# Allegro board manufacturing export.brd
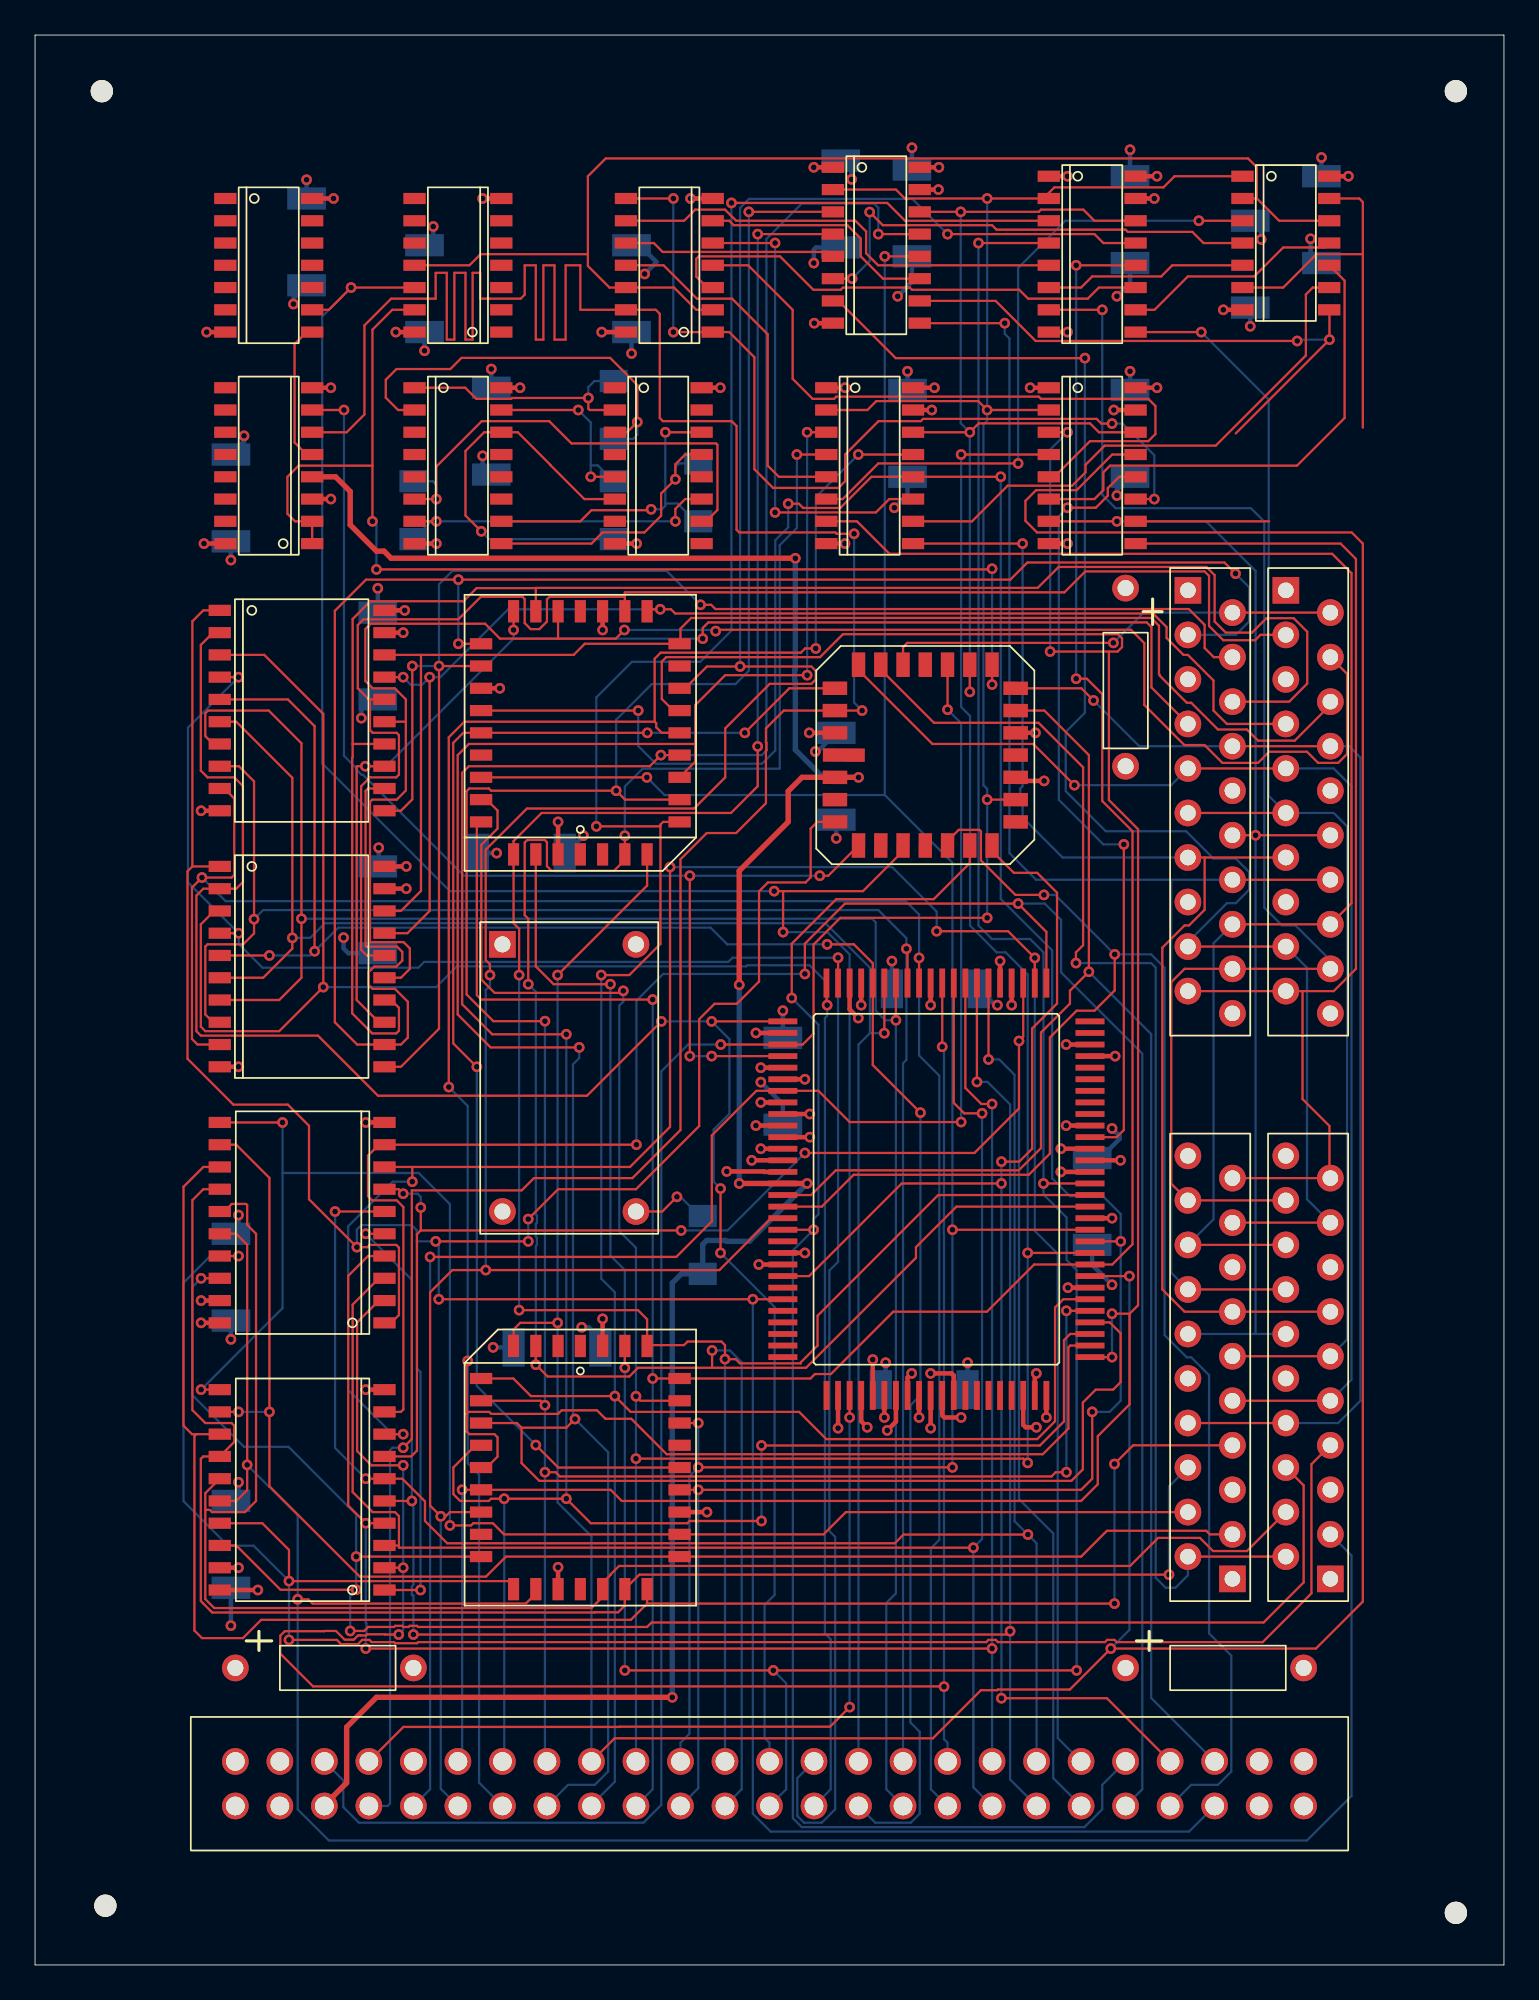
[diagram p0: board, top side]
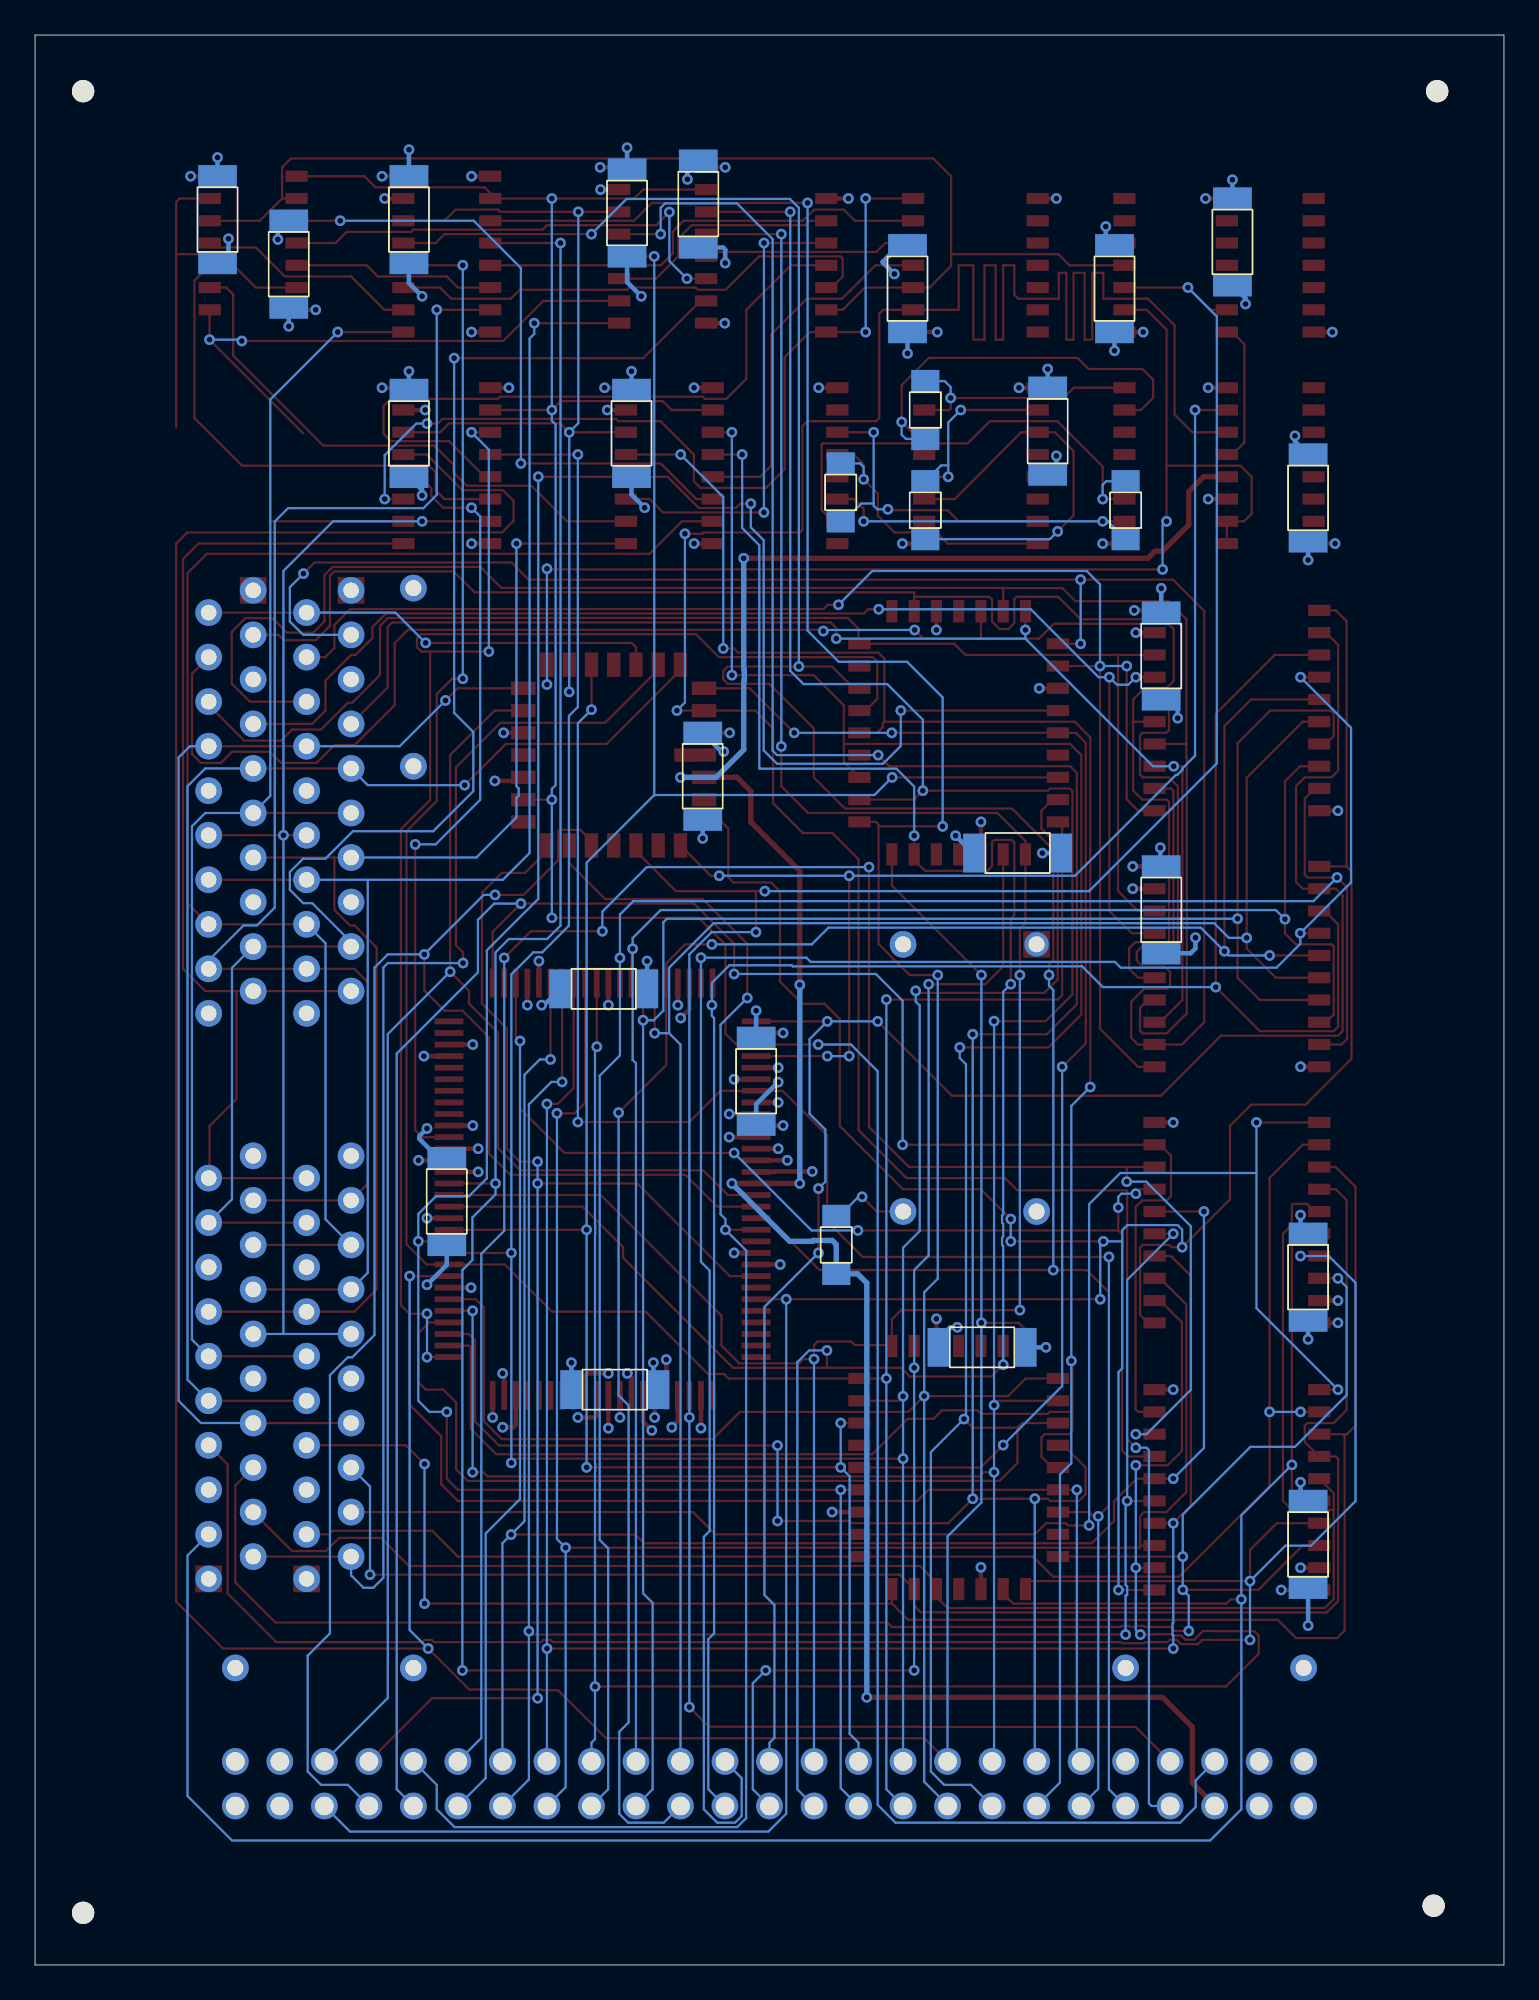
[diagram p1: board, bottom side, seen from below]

Outline 83.82 x 110.08 mm; copper layers: TOP, GND, VCC, BOTTOM. Coordinates in mm from the lower left corner of the outline.
Outline path: 0,110.08 83.82,110.08 83.82,0 0,0 0,110.08

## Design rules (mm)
constraint set DEFAULT: min track width 0.127
net group @PROJECT1_LIB.ESDESIGN(S_UPREV1: nets RA0 RA1 RA2 RA3 RA4 RA5 RA6 RA7 RA8 RA9 RA10 RA11 RA12 RA13 RA14 RA15
net group @PROJECT1_LIB.ESDESIGN(S_UPREV2: nets DATA0 DATA1 DATA2 DATA3 DATA4 DATA5 DATA6 DATA7 DATA8 DATA9 DATA10 DATA11 DATA12 DATA13 DATA14 DATA15
net group @PROJECT1_LIB.ESDESIGN(S_UPREV3: nets ADDR0 ADDR1 ADDR2 ADDR3 ADDR4 ADDR5 ADDR6 ADDR7
net group @PROJECT1_LIB.ESDESIGN(SCH_1):A: nets A1 A2 A3 A4 A5 A6 A7 A8 A9 A10 A11 A12 A13 A14 A15 A16
net group @PROJECT1_LIB.ESDESIGN(SCH_1):D: nets D0 D1 D2 D3 D4 D5 D6 D7 D8 D9 D10 D11 D12 D13 D14 D15
net group CLOCK: nets CLK1+ CLK1- CLK2+ CLK2- CLK3+ CLK3- CLK4+ CLK4-
net group SYNC: nets CLK2
nets with their own width: min track width 0.254; nets GND VCC

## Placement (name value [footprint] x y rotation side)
C1  .01UF  [SMDCAP]  50.8 32.82 0 bottom
C2  .01UF  [SMDCAP]  49.78 87.3 270 bottom
C3  .01UF  [SMDCAP]  62.48 99.49 270 bottom
C4  .01UF  [SMDCAP]  50.04 99.87 270 bottom
C5  22UF  [CAP400]  62.23 78.54 180 top
C6  .01UF  [SMDCAP]  45.97 100.51 90 bottom
C7  .01UF  [SMDCAP]  62.48 87.3 270 bottom
C8  22UF  [CAP400]  11.43 16.94 270 top
C9  .01UF  [SMDCAP]  60.33 43.61 90 bottom
C10  .01UF  [SMDCAP]  51.44 55.68 0 bottom
C11  22UF  [CAP400]  62.23 16.94 270 top
C12  .01UF  [SMDCAP]  26.04 87.43 270 bottom
C13  .01UF  [SMDCAP]  22.23 95.68 90 bottom
C14  1UF  [SMDCAP]  15.49 98.22 270 bottom
C15  .01UF  [SMDCAP]  11.18 83.74 90 bottom
C16  .01UF  [SMDCAP]  42.67 50.47 90 bottom
C17  1UF  [SMDCAP]  34.04 95.68 90 bottom
C18  .01UF  [SMDCAP]  29.72 35.23 180 bottom
C19  .01UF  [SMDCAP]  11.18 24.05 90 bottom
C20  1UF  [SMDCAP]  19.56 60.12 270 bottom
C21  .01UF  [SMDCAP]  27.69 63.42 180 bottom
C22  .01UF  [SMDCAP]  11.18 39.29 90 bottom
C23  .01UF  [SMDCAP]  19.56 74.6 270 bottom
C24  .01UF  [SMDCAP]  73.41 99.49 270 bottom
C25  .01UF  [SMDCAP]  45.72 67.74 270 bottom
C26  .01UF  [SMDCAP]  69.34 96.95 270 bottom
J1  -  [CONN50]  11.43 9.07 0 top
NOREF  -  [unnamed]  81.08 106.88 0 top
NOREF#2  -  [#2]  -43.18 -65.61 0 top
NOREF#3  -  [#2]  129.54 56.31 0 top
NOREF#4  -  [unnamed]  3.81 106.88 0 top
NOREF#5  -  [unnamed]  4.01 3.38 0 top
NOREF#6  -  [unnamed]  81.08 2.97 0 top
R1  10K  [SMDRES]  38.1 41.07 270 bottom
R2  10K  [SMDRES]  33.02 88.7 270 bottom
R3  10K  [SMDRES]  33.02 82.98 90 bottom
R4  10K  [SMDRES]  21.59 82.98 270 bottom
R5  10K  [SMDRES]  37.85 84 90 bottom
U1  ***  [SOIC16]  47.62 85.52 0 top
U2  ***  [SOIC16]  60.33 97.59 0 top
U3  ***  [SOIC16]  48.01 98.09 0 top
U4  ***  [SOIC16]  60.33 85.52 0 top
U5  ***  [ZIP20]  68.33 22.02 180 top
U6  ***  [ZIP20]  73.91 22.02 180 top
U7  ***  [ZIP20]  65.79 78.41 0 top
U8  ***  [ZIP20]  71.37 78.41 0 top
U9  ***  [SOIC14]  13.34 96.95 0 top
U10  ***  [SOIC16]  13.34 85.52 180 top
U11  ***  [PQFP100]  51.44 44.25 0 top
U12  ***  [SOIC14]  36.2 96.95 180 top
U13  ***  [PLCC32]  31.11 28.37 0 top
U14  ***  [SOIC20W]  15.24 27.1 180 top
U15  ***  [SOIC20W]  15.24 56.95 0 top
U16  ***  [PLCC32]  31.11 70.28 180 top
U17  ***  [SOIC20W]  15.24 42.34 180 top
U18  ***  [SOIC20W]  15.24 71.55 0 top
U19  ***  [LCC28]  50.8 69.01 90 top
U20  ***  [SOIC14]  71.37 98.22 0 top
U21  ***  [SOIC14]  24.13 96.95 180 top
U22  ***  [SOIC16]  35.56 85.52 0 top
U23  ***  [SOIC16]  24.13 85.52 0 top
Y1  ***  [CRYS14]  26.67 58.22 0 top

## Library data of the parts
C1-C4 C6 C7 C9 C10 C12 C13 C15 C16 C18 C19 C21-C26 = CAP: Tolerance: ***; User Part Number: 21505-267-01; part number: CAP-.01UF
C5 C8 C11 = CAP: Tolerance: ***; User Part Number: 21505-274-01; part number: CAP-22UF
C14 C17 C20 = CAP: Tolerance: ***; User Part Number: 21503-260-12; part number: CAP-1UF
J1 = CONNECTOR: User Part Number: ***
R1-R5 = PRES: Tolerance: ***; User Part Number: 24707-008-73; part number: PRES-10K
U1-U4 = 74F153: User Part Number: CDS_K006; part number: 74F153_SOIC-BASE; room: ADDR
U5-U8 = M5M44C256P-10: User Part Number: CDS_032; part number: M5M44C256P-10_ZIP-BASE; room: DRAM
U9 = 74F04: User Part Number: CDS_K002; part number: 74F04_SOIC-BASE
U10 = 74F109: User Part Number: CDS_K004; part number: 74F109_SOIC-BASE
U11 = I80386S: User Part Number: CDS_011; part number: I80386S_PQFP-BASE
U12 = 74F393: User Part Number: CDS_K012; alternate symbols: (TOP:DIP14_3;BOTTOM:SOIC14_PE); part number: 74F393_SOIC-BASE
U13 U16 = 27C256: User Part Number: CDS_002; part number: 27C256_PLCC-BASE
U14 U15 U17 U18 = 74F245: User Part Number: CDS_K008; part number: 74F245_SOIC-BASE
U19 = PAL20R8: User Part Number: cds_028; part number: PAL20R8_LCC-BASE
U20 = 74F393: User Part Number: CDS_K012; part number: 74F393_SOIC-BASE
U21 = 74F32: User Part Number: CDS_K010; part number: 74F32_SOIC-BASE
U22 = DS90LV031TM
U23 = DS90LV032TM
Y1 = OSC

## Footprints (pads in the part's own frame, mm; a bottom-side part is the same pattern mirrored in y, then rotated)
CAP400
  round 1.524 hole 0.914: 1(0,0) 2(0,10.16)
CONN50
  round 1.524 hole 1.067: 1(0,0) 2(0,2.54) 3(2.54,0) 4(2.54,2.54) 5(5.08,0) 6(5.08,2.54) 7(7.62,0) 8(7.62,2.54) 9(10.16,0) 10(10.16,2.54) 11(12.7,0) 12(12.7,2.54) 13(15.24,0) 14(15.24,2.54) 15(17.78,0) 16(17.78,2.54) 17(20.32,0) 18(20.32,2.54) 19(22.86,0) 20(22.86,2.54) 21(25.4,0) 22(25.4,2.54) 23(27.94,0) 24(27.94,2.54) 25(30.48,0) 26(30.48,2.54) 27(33.02,0) 28(33.02,2.54) 29(35.56,0) 30(35.56,2.54) 31(38.1,0) 32(38.1,2.54) 33(40.64,0) 34(40.64,2.54) 35(43.18,0) 36(43.18,2.54) 37(45.72,0) 38(45.72,2.54) 39(48.26,0) 40(48.26,2.54) 41(50.8,0) 42(50.8,2.54) 43(53.34,0) 44(53.34,2.54) 45(55.88,0) 46(55.88,2.54) 47(58.42,0) 48(58.42,2.54) 49(60.96,0) 50(60.96,2.54)
CRYS14
  rect 1.524x1.524 hole 0.914: 1(0,0)
  round 1.524 hole 0.914: 7(0,-15.24) 8(7.62,-15.24) 14(7.62,0)
LCC28
  rect 0.762x2.388 smd rot 179.7: 1(0,4.648)
  rect 0.762x1.397 smd rot 179.7: 2(-1.27,5.156) 12(-3.81,-5.156) 13(-2.54,-5.156) 14(-1.27,-5.156) 17(2.54,-5.156) 18(3.81,-5.156)
  rect 0.762x1.397 smd: 3(-2.54,5.156) 4(-3.81,5.156) 15(0,-5.156) 16(1.27,-5.156) 26(3.81,5.156) 27(2.54,5.156) 28(1.27,5.156)
  rect 0.762x1.397 smd rot 89.7: 5(-5.156,3.81) 6(-5.156,2.54) 7(-5.156,1.27) 8(-5.156,0) 9(-5.156,-1.27)
  rect 1.397x0.762 smd: 10(-5.156,-2.54) 11(-5.156,-3.81) 19(5.156,-3.81) 20(5.156,-2.54) 21(5.156,-1.27) 22(5.156,0) 23(5.156,1.27) 24(5.156,2.54) 25(5.156,3.81)
PLCC32
  rect 0.635x1.27 smd: 1(0,6.934) 2(-1.27,6.934) 3(-2.54,6.934) 4(-3.81,6.934) 14(-3.81,-6.934) 15(-2.54,-6.934) 16(-1.27,-6.934) 17(0,-6.934) 18(1.27,-6.934) 19(2.54,-6.934) 20(3.81,-6.934) 30(3.81,6.934) 31(2.54,6.934) 32(1.27,6.934)
  rect 1.27x0.635 smd: 5(-5.664,5.08) 6(-5.664,3.81) 7(-5.664,2.54) 8(-5.664,1.27) 9(-5.664,0) 10(-5.664,-1.27) 11(-5.664,-2.54) 12(-5.664,-3.81) 13(-5.664,-5.08) 21(5.664,-5.08) 22(5.664,-3.81) 23(5.664,-2.54) 24(5.664,-1.27) 25(5.664,0) 26(5.664,1.27) 27(5.664,2.54) 28(5.664,3.81) 29(5.664,5.08)
PQFP100
  rect 1.651x0.33 smd: 1(-8.763,9.576) 2(-8.763,8.915) 3(-8.763,8.255) 4(-8.763,7.595) 5(-8.763,6.934) 6(-8.763,6.274) 7(-8.763,5.613) 8(-8.763,4.953) 9(-8.763,4.293) 10(-8.763,3.632) 11(-8.763,2.972) 12(-8.763,2.311) 13(-8.763,1.651) 14(-8.763,0.991) 15(-8.763,0.33) 16(-8.763,-0.33) 17(-8.763,-0.991) 18(-8.763,-1.651) 19(-8.763,-2.311) 20(-8.763,-2.972) 21(-8.763,-3.632) 22(-8.763,-4.293) 23(-8.763,-4.953) 24(-8.763,-5.613) 25(-8.763,-6.274) 26(-8.763,-6.934) 27(-8.763,-7.595) 28(-8.763,-8.255) 29(-8.763,-8.915) 30(-8.763,-9.576) 51(8.763,-9.576) 52(8.763,-8.915) 53(8.763,-8.255) 54(8.763,-7.595) 55(8.763,-6.934) 56(8.763,-6.274) 57(8.763,-5.613) 58(8.763,-4.953) 59(8.763,-4.293) 60(8.763,-3.632) 61(8.763,-2.972) 62(8.763,-2.311) 63(8.763,-1.651) 64(8.763,-0.991) 65(8.763,-0.33) 66(8.763,0.33) 67(8.763,0.991) 68(8.763,1.651) 69(8.763,2.311) 70(8.763,2.972) 71(8.763,3.632) 72(8.763,4.293) 73(8.763,4.953) 74(8.763,5.613) 75(8.763,6.274) 76(8.763,6.934) 77(8.763,7.595) 78(8.763,8.255) 79(8.763,8.915) 80(8.763,9.576)
  rect 0.33x1.651 smd: 31(-6.274,-11.76) 32(-5.613,-11.76) 33(-4.953,-11.76) 34(-4.293,-11.76) 35(-3.632,-11.76) 36(-2.972,-11.76) 37(-2.311,-11.76) 38(-1.651,-11.76) 39(-0.991,-11.76) 40(-0.33,-11.76) 41(0.33,-11.76) 42(0.991,-11.76) 43(1.651,-11.76) 44(2.311,-11.76) 45(2.972,-11.76) 46(3.632,-11.76) 47(4.293,-11.76) 48(4.953,-11.76) 49(5.613,-11.76) 50(6.274,-11.76) 81(6.274,11.76) 82(5.613,11.76) 83(4.953,11.76) 84(4.293,11.76) 85(3.632,11.76) 86(2.972,11.76) 87(2.311,11.76) 88(1.651,11.76) 89(0.991,11.76) 90(0.33,11.76) 91(-0.33,11.76) 92(-0.991,11.76) 93(-1.651,11.76) 94(-2.311,11.76) 95(-2.972,11.76) 96(-3.632,11.76) 97(-4.293,11.76) 98(-4.953,11.76) 99(-5.613,11.76) 100(-6.274,11.76)
SMDCAP
  rect 1.27x2.21 smd: 1(-2.54,0) 2(2.413,0)
SMDRES
  rect 1.27x1.6 smd: 1(-1.651,0) 2(1.651,0)
SOIC14
  rect 1.27x0.635 smd: 1(-2.477,3.81) 2(-2.477,2.54) 3(-2.477,1.27) 4(-2.477,0) 5(-2.477,-1.27) 6(-2.477,-2.54) 7(-2.477,-3.81) 8(2.477,-3.81) 9(2.477,-2.54) 10(2.477,-1.27) 11(2.477,0) 12(2.477,1.27) 13(2.477,2.54) 14(2.477,3.81)
SOIC16
  rect 1.27x0.635 smd: 1(-2.477,4.445) 2(-2.477,3.175) 3(-2.477,1.905) 4(-2.477,0.635) 5(-2.477,-0.635) 6(-2.477,-1.905) 7(-2.477,-3.175) 8(-2.477,-4.445) 9(2.477,-4.445) 10(2.477,-3.175) 11(2.477,-1.905) 12(2.477,-0.635) 13(2.477,0.635) 14(2.477,1.905) 15(2.477,3.175) 16(2.477,4.445)
SOIC20W
  rect 1.27x0.635 smd: 1(-4.699,5.715) 2(-4.699,4.445) 3(-4.699,3.175) 4(-4.699,1.905) 5(-4.699,0.635) 6(-4.699,-0.635) 7(-4.699,-1.905) 8(-4.699,-3.175) 9(-4.699,-4.445) 10(-4.699,-5.715) 11(4.699,-5.715) 12(4.699,-4.445) 13(4.699,-3.175) 14(4.699,-1.905) 15(4.699,-0.635) 16(4.699,0.635) 17(4.699,1.905) 18(4.699,3.175) 19(4.699,4.445) 20(4.699,5.715)
unnamed
  round 1.27 hole 6.35 unplated: (0,0)
ZIP20
  rect 1.524x1.524 hole 0.889: 1(0,0)
  round 1.524 hole 0.889: 2(2.54,-1.27) 3(0,-2.54) 4(2.54,-3.81) 5(0,-5.08) 6(2.54,-6.35) 7(0,-7.62) 8(2.54,-8.89) 9(0,-10.16) 10(2.54,-11.43) 11(0,-12.7) 12(2.54,-13.97) 13(0,-15.24) 14(2.54,-16.51) 15(0,-17.78) 16(2.54,-19.05) 17(0,-20.32) 18(2.54,-21.59) 19(0,-22.86) 20(2.54,-24.13)

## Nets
GND: C1.2(B<0>) C2.2(B<0>) C3.2(B<0>) C4.2(B<0>) C5.2(B<0>) C6.2(B<0>) C7.2(B<0>) C8.2(B<0>) C9.2(B<0>) C10.2(B<0>) C11.2(B<0>) C12.2(B<0>) C13.2(B<0>) C14.2(B<0>) C15.2(B<0>) C16.2(B<0>) C17.2(B<0>) C18.2(B<0>) C19.2(B<0>) C20.2(B<0>) C21.2(B<0>) C22.2(B<0>) C23.2(B<0>) C24.2(B<0>) C25.2(B<0>) C26.2(B<0>) J1.47 J1.48 J1.49 J1.50 U1.1 U1.8 U1.15 U2.1 U2.8 U2.15 U3.1 U3.8 U3.15 U4.1 U4.8 U4.15 U5.1 U5.5 U5.20 U6.1 U6.5 U6.20 U7.1 U7.5 U7.20 U8.1 U8.5 U8.20 U9.7 U10.3 U10.8 U11.2 U11.5 U11.11 U11.12 U11.13 U11.14 U11.22 U11.35 U11.37 U11.38 U11.40 U11.41 U11.49 U11.50 U11.63 U11.67 U11.68 U11.77 U11.78 U11.85 U11.98 U12.7 U13.16 U13.23 U14.10 U14.19 U15.10 U15.19 U16.16 U16.23 U17.10 U17.19 U18.10 U18.19 U19.14 U19.16(OE*) U20.7 U21.7 U22.8 U23.8 Y1.1 Y1.7
VCC: C1.1 C2.1 C3.1 C4.1 C5.1 C6.1 C7.1 C8.1 C9.1 C10.1 C11.1 C12.1 C13.1 C14.1 C15.1 C16.1 C17.1 C18.1 C19.1 C20.1 C21.1 C22.1 C23.1 C24.1 C25.1 C26.1 J1.1 J1.2 J1.3 J1.4 U1.16 U2.16 U3.16 U4.16 U5.15 U6.15 U7.15 U8.15 U9.14 U10.16 U11.6 U11.8 U11.9 U11.10 U11.21 U11.32 U11.34 U11.36 U11.39 U11.42 U11.48 U11.57 U11.69 U11.71 U11.84 U11.91 U11.97 U12.14 U13.32 U14.20 U15.20 U16.32 U17.20 U18.20 U19.28 U20.14 U21.14 U22.16 U23.16 Y1.14
A1: J1.11 U2.13 U11.18 U13.11 U16.11
A2: J1.12 U4.3 U11.51 U13.10 U16.10
A3: J1.13 U1.13 U11.52 U13.9 U16.9
A4: J1.14 U3.13 U11.53 U13.8 U16.8
A5: J1.15 U1.3 U11.54 U13.7 U16.7
A6: J1.16 U3.3 U11.55 U13.6 U16.6
A7: J1.17 U2.3 U11.56 U13.5 U16.5
A8: J1.18 U4.13 U11.58 U13.4 U16.4
A9: J1.19 U2.12 U11.59 U13.29 U16.29
A10: J1.20 U4.4 U11.60 U13.28 U16.28
A11: J1.21 U1.12 U11.61 U13.24 U16.24
A12: J1.22 U3.12 U11.62 U13.27 U16.27
A13: J1.23 U1.4 U11.64 U13.3 U16.3
A14: J1.24 U3.4 U11.65 U13.30 U16.30
A15: J1.25 U2.4 U11.66 U13.31 U16.31
A16: U4.12 U11.70
ADDR0: U2.9 U5.11 U6.11 U7.11 U8.11
ADDR1: U4.7(Y<0>) U5.12 U6.12 U7.12 U8.12
ADDR2: U1.9 U5.13 U6.13 U7.13 U8.13
ADDR3: U3.9 U5.14 U6.14 U7.14 U8.14
ADDR4: U1.7(Y<0>) U5.16 U6.16 U7.16 U8.16
ADDR5: U3.7(Y<0>) U5.17 U6.17 U7.17 U8.17
ADDR6: U2.7(Y<0>) U5.18 U6.18 U7.18 U8.18
ADDR7: U4.9 U5.19 U6.19 U7.19 U8.19
ADSL: J1.46 U11.16 U19.17
BHEL: J1.42 U11.19 U19.10
BLEL: J1.43 U11.17 U19.9
CAS0L: U5.2 U6.2 U19.24
CAS1L: U7.2 U8.2 U19.23
CLEAR: U10.1 U10.2 U19.19 U21.13
CLK1+: R2.1 U22.2 U23.1
CLK1-: R2.2(B<0>) U22.3 U23.2
CLK2: J1.5 R1.2(B<0>) U10.4 U11.15 U19.2
CLK2+: R3.1 U22.6 U23.14
CLK2-: R3.2(B<0>) U22.5 U23.15
CLK3+: R4.1 U22.10 U23.6
CLK3-: R4.2(B<0>) U22.11 U23.7
CLK4+: R5.1 U22.14 U23.10
CLK4-: R5.2(B<0>) U22.13 U23.9
CLRCNT: U12.2 U12.12 U20.2 U20.12 U21.11
D0: J1.26 U11.1 U15.2 U18.2
D1: J1.27 U11.100 U15.3 U18.3
D2: J1.28 U11.99 U15.4 U18.4
D3: J1.29 U11.96 U15.5 U18.5
D4: J1.30 U11.95 U15.6 U18.6
D5: J1.31 U11.94 U15.7 U18.7
D6: J1.32 U11.93 U15.8 U18.8
D7: J1.33 U11.92 U15.9 U18.9
D8: J1.34 U11.90 U14.2 U17.2
D9: J1.35 U11.89 U14.3 U17.3
D10: J1.36 U11.88 U14.4 U17.4
D11: J1.37 U11.87 U14.5 U17.5
D12: J1.38 U11.86 U14.6 U17.6
D13: J1.39 U11.83 U14.7 U17.7
D14: J1.40 U11.82 U14.8 U17.8
D15: J1.41 U11.81 U14.9 U17.9
DATA0: U8.6 U15.18(B<0>) U16.13 U18.18(B<0>)
DATA1: U8.7 U15.17 U16.14 U18.17
DATA2: U8.3 U15.16 U16.15 U18.16
DATA3: U8.4 U15.15 U16.18 U18.15
DATA4: U7.6 U15.14 U16.19 U18.14
DATA5: U7.7 U15.13 U16.20 U18.13
DATA6: U7.3 U15.12 U16.21 U18.12
DATA7: U7.4 U15.11 U16.22 U18.11
DATA8: U6.6 U13.13 U14.18(B<0>) U17.18(B<0>)
DATA9: U6.7 U13.14 U14.17 U17.17
DATA10: U6.3 U13.15 U14.16 U17.16
DATA11: U6.4 U13.18 U14.15 U17.15
DATA12: U5.6 U13.19 U14.14 U17.14
DATA13: U5.7 U13.20 U14.13 U17.13
DATA14: U5.3 U13.21 U14.12 U17.12
DATA15: U5.4 U13.22 U14.11 U17.11
HLDA: J1.6 U1.2 U2.2 U3.2 U4.2 U11.3 U19.13 U20.1
M_IO: J1.44 U11.23 U19.11
MUXSOL: U1.14 U2.14 U3.14 U4.14 U19.20
PCLK: J1.7 U10.6(Q<0>) U12.13 U19.27
RA0: U2.11 U12.3
RA1: U4.5 U12.4
RA2: U1.11 U12.5
RA3: U3.11 U12.6(Q<3>)
RA4: U1.5 U12.11
RA5: U3.5 U12.10
RA6: U2.5 U12.9
RA7: U4.11 U12.1 U12.8
RA8: U2.10 U20.11
RA9: U4.6 U20.10
RA10: U1.10 U20.9
RA11: U3.10 U20.8
RA12: U1.6 U20.3
RA13: U3.6 U20.4
RA14: U2.6 U20.5
RA15: U4.10 U20.6(Q<3>) U20.13
RASL: U5.9 U6.9 U7.9 U8.9 U19.25
RDYL: J1.9(A<9>) U11.7 U19.21
REF: U10.7 U11.4 U19.5
RESET: J1.8 U9.9 U11.33 U19.7 U21.12
RESETL: U9.8 U10.5
ROMOEL: U13.25 U16.25 U19.26
UNNAMED_1_OSC_I31_B: R1.1 Y1.8(B)
W_R: J1.45 U11.25(W/R*) U14.1 U15.1 U17.1 U18.1 U19.4
WEL: U5.8(WE*) U6.8(WE*) U7.8(WE*) U8.8(WE*) U19.18

Pads without a net: J1 10; U5 10; U6 10; U7 10; U8 10; U9 1 2 3 4 5 6 10 11 12 13; U10 9 10 11 12 13 14 15; U11 20 24 26 27 28 29 30 31 43 44 45 46 47 72 73 74 75 76 79 80; U13 1 2 12 17 26; U16 1 2 12 17 26; U19 1 3 6 8 12 15 22; U21 1 2 3 4 5 6 8 9 10; U22 1 4 7 9 12 15; U23 3 4 5 11 12 13

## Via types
v1: diameter 0.61, hole 0.33, TOP to BOTTOM, 390 vias

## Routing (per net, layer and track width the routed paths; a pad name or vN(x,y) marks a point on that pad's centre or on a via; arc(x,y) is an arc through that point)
GND: length 353.4
  TOP w0.254: U11.41 51.77,31.36 51.89,31.23 v1(52.84,31.23) ; U20.7 v1(67.81,94.41) ; U11.50 v1(57.71,31.23) ; U19.16 v1(57.09,70.28) ; U18.10 v1(9.47,65.84) ; U12.7 v1(37.41,100.76) ; U4.1 v1(56.78,89.97) ; U2.15 v1(63.87,100.76) ; U11.85 v1(55.07,57.26) ; U11.77 v1(61.63,51.84) ; U16.16 v1(32.38,76.15) ; U11.68 v1(61.94,45.9) ; U13.23 v1(38.34,25.83) ; U11.63 v1(61.46,42.6) ; U16.23 v1(26.52,72.82) ; U11.35 v1(47.8,34.53) ; v1(57.14,33.74) 57.05,33.66 U11.49 ; U22.8 v1(34.33,81.08) ; U14.10 v1(18.87,32.82) ; U3.15 v1(51.55,101.27) ; U11.67 v1(58.53,45.24) ; v1(48.63,30.49) 49.12,30.99 U11.37 ; U23.8 v1(22.9,81.08) ; U11.5 v1(41.41,51.18) ; v1(57.58,67.54) 56.16,67.54 U19.14 ; U1.8 v1(46.22,81.08) ; U15.19 v1(21.18,61.39) ; U11.38 49.78,33.5 v1(50.03,33.74) ; U11.13 v1(40.89,45.9) ; U13.16 v1(29.84,22.68) ; U4.8 v1(58.92,81.08) ; U17.19 v1(9.47,37.9) ; U11.40 v1(51.1,30.62) ; U2.8 v1(58.92,93.14) ; U1.15 v1(51.17,88.7) ; U9.7 v1(9.79,93.14) ; U1.1 v1(46.22,89.97) ; U4.15 v1(61.56,88.7) ; U3.8 v1(44.46,93.65) ; U18.19 v1(21.01,76) ; U10.3 v1(16.88,83.62) ; U11.22 v1(41.3,39.95) ; U11.98 46.48,54.51 v1(46.98,54.01) ; U15.10 v1(11.61,51.23) ; U11.78 v1(58.84,52.5) ; U11.11 v1(44.21,47.22) ; U14.19 v1(11.61,22.66) ; U11.2 v1(41.14,53.16) ; U21.7 v1(25.54,100.76) ; v1(39.47,45.26) 41.59,45.26 41.62,45.24 U11.14 ; U10.8 v1(16.88,89.97) ; U3.1 v1(44.44,102.54) ; U11.12 v1(41.41,46.56) ; U17.10 v1(18.87,48.06) ; U2.1 v1(58.92,102.03)
  GND w0.254: v1(41.3,39.95) 41.71,40.36 ; v1(41.3,39.95) 41.71,39.54 ; v1(41.3,39.95) 40.89,40.36 ; v1(41.3,39.95) 40.89,39.54 ; v1(61.46,47.71) 61.87,48.12 ; v1(61.46,47.71) 61.87,47.3 ; v1(61.46,47.71) 61.04,48.12 ; v1(61.46,47.71) 61.04,47.3 ; 45.31,63.85 v1(45.72,64.26) ; v1(45.72,64.26) 46.13,63.85 ; v1(45.72,64.26) 46.13,64.67 ; v1(45.72,64.26) 45.31,64.67 ; 49.61,34.15 v1(50.03,33.74) ; v1(50.03,33.74) 50.44,33.33 ; v1(50.03,33.74) 49.61,33.33 ; v1(50.03,33.74) 50.44,34.15 ; v1(14.74,94.74) 15.16,94.33 ; v1(14.74,94.74) 15.16,95.15 ; v1(14.74,94.74) 14.33,94.33 ; v1(14.74,94.74) 14.33,95.15 ; 37.93,25.42 v1(38.34,25.83) ; v1(38.34,25.83) 38.75,25.42 ; v1(38.34,25.83) 37.93,26.24 ; v1(38.34,25.83) 38.75,26.24 ; v1(55.07,57.26) 55.48,56.85 ; v1(55.07,57.26) 54.66,57.67 ; v1(55.07,57.26) 55.48,57.67 ; v1(55.07,57.26) 54.66,56.85 ; v1(46.6,101.85) 47.01,102.26 ; v1(46.6,101.85) 46.19,102.26 ; v1(46.6,101.85) 46.19,101.44 ; v1(46.6,101.85) 47.01,101.44 ; v1(49.23,95.19) 49.64,95.6 ; v1(49.23,95.19) 48.81,95.6 ; v1(49.23,95.19) 49.64,94.78 ; v1(49.23,95.19) 48.81,94.78 ; 18.46,32.41 v1(18.87,32.82) ; v1(18.87,32.82) 18.46,33.23 ; v1(18.87,32.82) 19.28,33.23 ; v1(18.87,32.82) 19.28,32.41 ; 44.03,102.13 v1(44.44,102.54) ; v1(44.44,102.54) 44.85,102.13 ; v1(44.44,102.54) 44.03,102.95 ; v1(44.44,102.54) 44.85,102.95 ; 73.91,53.15 U8.20 ; U8.20 75.04,54.28 ; U8.20 72.78,54.28 ; U8.20 73.91,55.41 ; v1(72.78,98.46) 73.19,98.05 ; v1(72.78,98.46) 72.37,98.87 ; v1(72.78,98.46) 73.19,98.87 ; v1(72.78,98.46) 72.37,98.05 ; v1(44.46,93.65) 44.87,94.06 ; v1(44.46,93.65) 44.05,93.24 ; v1(44.46,93.65) 44.87,93.24 ; v1(44.46,93.65) 44.05,94.06 ; v1(51.17,88.7) 51.58,88.29 ; v1(51.17,88.7) 50.76,89.11 ; v1(51.17,88.7) 50.76,88.29 ; v1(51.17,88.7) 51.58,89.11 ; 51.14,101.68 v1(51.55,101.27) ; v1(51.55,101.27) 51.96,101.68 ; v1(51.55,101.27) 51.14,100.86 ; v1(51.55,101.27) 51.96,100.86 ; v1(53.21,34.35) 53.62,33.94 ; v1(53.21,34.35) 53.62,34.76 ; v1(53.21,34.35) 52.8,33.94 ; v1(53.21,34.35) 52.8,34.76 ; v1(61.46,42.6) 61.87,42.19 ; v1(61.46,42.6) 61.87,43.01 ; v1(61.46,42.6) 61.04,43.01 ; v1(61.46,42.6) 61.04,42.19 ; 26.11,73.23 v1(26.52,72.82) ; v1(26.52,72.82) 26.93,73.23 ; v1(26.52,72.82) 26.93,72.41 ; v1(26.52,72.82) 26.11,72.41 ; v1(61.73,83.82) 62.15,83.41 ; v1(61.73,83.82) 61.32,84.23 ; v1(61.73,83.82) 61.32,83.41 ; v1(61.73,83.82) 62.15,84.23 ; 61.53,46.31 v1(61.94,45.9) ; v1(61.94,45.9) 61.53,45.49 ; v1(61.94,45.9) 62.35,45.49 ; v1(61.94,45.9) 62.35,46.31 ; 20.6,75.59 v1(21.01,76) ; v1(21.01,76) 21.42,75.59 ; v1(21.01,76) 21.42,76.41 ; v1(21.01,76) 20.6,76.41 ; v1(26.14,35.23) 26.55,34.82 ; v1(26.14,35.23) 25.73,34.82 ; v1(26.14,35.23) 26.55,35.64 ; v1(26.14,35.23) 25.73,35.64 ; C5.2 63.4,68.38 ; C5.2 62.23,69.55 ; C5.2 61.06,68.38 ; C5.2 62.23,67.21 ; v1(58.92,102.03) 59.33,102.44 ; v1(58.92,102.03) 58.5,101.62 ; v1(58.92,102.03) 59.33,101.62 ; v1(58.92,102.03) 58.5,102.44 ; 68.93,93.88 v1(69.34,93.47) ; v1(69.34,93.47) 69.75,93.06 ; v1(69.34,93.47) 69.75,93.88 ; v1(69.34,93.47) 68.93,93.06 ; v1(9.79,93.14) 10.2,92.73 ; v1(9.79,93.14) 9.38,93.55 ; v1(9.79,93.14) 9.38,92.73 ; v1(9.79,93.14) 10.2,93.55 ; v1(58.92,81.08) 59.33,81.49 ; v1(58.92,81.08) 58.5,80.67 ; v1(58.92,81.08) 58.5,81.49 ; v1(58.92,81.08) 59.33,80.67 ; v1(67.81,94.41) 68.22,94.82 ; v1(67.81,94.41) 67.39,94.82 ; v1(67.81,94.41) 68.22,94 ; v1(67.81,94.41) 67.39,94 ; v1(29.84,22.68) 30.26,23.09 ; v1(29.84,22.68) 30.26,22.27 ; v1(29.84,22.68) 29.43,23.09 ; v1(29.84,22.68) 29.43,22.27 ; v1(56.78,89.97) 57.19,89.56 ; v1(56.78,89.97) 56.37,90.38 ; v1(56.78,89.97) 57.19,90.38 ; v1(56.78,89.97) 56.37,89.56 ; 20.77,61.8 v1(21.18,61.39) ; v1(21.18,61.39) 20.77,60.98 ; v1(21.18,61.39) 21.59,60.98 ; v1(21.18,61.39) 21.59,61.8 ; 22.31,98.75 v1(22.72,99.16) ; v1(22.72,99.16) 22.31,99.57 ; v1(22.72,99.16) 23.13,99.57 ; v1(22.72,99.16) 23.13,98.75 ; 67.2,27.1 U5.5 ; U5.5 68.33,25.97 ; U5.5 68.33,28.23 ; U5.5 69.46,27.1 ; U7.20 68.33,55.41 ; U7.20 67.2,54.28 ; U7.20 68.33,53.15 ; U7.20 69.46,54.28 ; 54.5,54.34 v1(54.91,54.75) ; v1(54.91,54.75) 54.5,55.16 ; v1(54.91,54.75) 55.33,54.34 ; v1(54.91,54.75) 55.33,55.16 ; 72.39,8.06 J1.49 ; J1.49 71.39,9.07 ; J1.49 73.39,9.07 ; J1.49 72.39,10.07 ; Y1.1 27.67,58.22 ; Y1.1 26.67,59.22 ; Y1.1 25.67,58.22 ; Y1.1 26.67,57.21 ; 25.13,86.49 v1(25.54,86.08) ; v1(25.54,86.08) 25.13,85.67 ; v1(25.54,86.08) 25.95,85.67 ; v1(25.54,86.08) 25.95,86.49 ; 31.97,75.74 v1(32.38,76.15) ; v1(32.38,76.15) 32.8,75.74 ; v1(32.38,76.15) 32.8,76.56 ; v1(32.38,76.15) 31.97,76.56 ; U6.20 71.37,47.28 ; U6.20 71.37,45.02 ; U6.20 70.24,46.15 ; U6.20 72.5,46.15 ; v1(25.54,100.76) 25.95,100.35 ; v1(25.54,100.76) 25.95,101.17 ; v1(25.54,100.76) 25.13,100.35 ; v1(25.54,100.76) 25.13,101.17 ; v1(41.41,51.18) 41.83,50.77 ; v1(41.41,51.18) 41.83,51.59 ; v1(41.41,51.18) 41,51.59 ; v1(41.41,51.18) 41,50.77 ; v1(16.88,83.62) 17.29,83.21 ; v1(16.88,83.62) 17.29,84.03 ; v1(16.88,83.62) 16.47,84.03 ; v1(16.88,83.62) 16.47,83.21 ; v1(9.47,65.84) 9.88,66.25 ; v1(9.47,65.84) 9.88,65.43 ; v1(9.47,65.84) 9.06,66.25 ; v1(9.47,65.84) 9.06,65.43 ; 58.12,44.83 v1(58.53,45.24) ; v1(58.53,45.24) 58.12,45.65 ; v1(58.53,45.24) 58.94,44.83 ; v1(58.53,45.24) 58.94,45.65 ; v1(57.58,67.54) 57.99,67.13 ; v1(57.58,67.54) 57.99,67.95 ; v1(57.58,67.54) 57.17,67.13 ; v1(57.58,67.54) 57.17,67.95 ; 16.47,90.38 v1(16.88,89.97) ; v1(16.88,89.97) 17.29,90.38 ; v1(16.88,89.97) 16.47,89.56 ; v1(16.88,89.97) 17.29,89.56 ; 11.2,22.25 v1(11.61,22.66) ; v1(11.61,22.66) 12.02,23.07 ; v1(11.61,22.66) 12.02,22.25 ; v1(11.61,22.66) 11.2,23.07 ; U7.5 65.79,74.46 ; U7.5 65.79,72.2 ; U7.5 66.92,73.33 ; U7.5 64.66,73.33 ; 71.37,72.2 U8.5 ; U8.5 70.24,73.33 ; U8.5 72.5,73.33 ; U8.5 71.37,74.46 ; 45.8,90.38 v1(46.22,89.97) ; v1(46.22,89.97) 46.63,90.38 ; v1(46.22,89.97) 45.8,89.56 ; v1(46.22,89.97) 46.63,89.56 ; J1.48 69.85,12.61 ; J1.48 70.85,11.61 ; J1.48 69.85,10.6 ; J1.48 68.85,11.61 ; v1(22.9,81.08) 23.31,80.67 ; v1(22.9,81.08) 22.49,81.49 ; v1(22.9,81.08) 23.31,81.49 ; v1(22.9,81.08) 22.49,80.67 ; v1(11.61,51.23) 12.02,50.82 ; v1(11.61,51.23) 12.02,51.64 ; v1(11.61,51.23) 11.2,50.82 ; v1(11.61,51.23) 11.2,51.64 ; v1(58.92,93.14) 59.33,93.55 ; v1(58.92,93.14) 58.5,92.73 ; v1(58.92,93.14) 59.33,92.73 ; v1(58.92,93.14) 58.5,93.55 ; v1(11.61,27.53) 12.02,27.94 ; v1(11.61,27.53) 12.02,27.12 ; v1(11.61,27.53) 11.2,27.12 ; v1(11.61,27.53) 11.2,27.94 ; 9.06,38.31 v1(9.47,37.9) ; v1(9.47,37.9) 9.88,38.31 ; v1(9.47,37.9) 9.88,37.49 ; v1(9.47,37.9) 9.06,37.49 ; v1(52.84,31.23) 53.26,31.64 ; v1(52.84,31.23) 52.43,30.82 ; v1(52.84,31.23) 52.43,31.64 ; v1(52.84,31.23) 53.26,30.82 ; v1(63.87,100.76) 64.28,100.35 ; v1(63.87,100.76) 63.46,101.17 ; v1(63.87,100.76) 64.28,101.17 ; v1(63.87,100.76) 63.46,100.35 ; U5.20 66.92,46.15 ; U5.20 65.79,47.28 ; U5.20 65.79,45.02 ; U5.20 64.66,46.15 ; 18.21,71.53 v1(18.62,71.12) ; v1(18.62,71.12) 18.21,70.71 ; v1(18.62,71.12) 19.03,71.53 ; v1(18.62,71.12) 19.03,70.71 ; 36.99,100.35 v1(37.41,100.76) ; v1(37.41,100.76) 37.82,101.17 ; v1(37.41,100.76) 37.82,100.35 ; v1(37.41,100.76) 36.99,101.17 ; 11.51,86.81 v1(11.93,87.22) ; v1(11.93,87.22) 12.34,87.63 ; v1(11.93,87.22) 11.51,87.63 ; v1(11.93,87.22) 12.34,86.81 ; v1(11.61,42.77) 12.02,42.36 ; v1(11.61,42.77) 11.2,42.36 ; v1(11.61,42.77) 11.2,43.18 ; v1(11.61,42.77) 12.02,43.18 ; v1(26.34,63.42) 26.75,63.83 ; v1(26.34,63.42) 25.93,63.01 ; v1(26.34,63.42) 26.75,63.01 ; v1(26.34,63.42) 25.93,63.83 ; 72.39,10.6 J1.50 ; J1.50 73.39,11.61 ; J1.50 71.39,11.61 ; J1.50 72.39,12.61 ; 48.62,83.53 v1(49.03,83.12) ; v1(49.03,83.12) 49.45,83.53 ; v1(49.03,83.12) 49.45,82.71 ; v1(49.03,83.12) 48.62,82.71 ; 72.39,15.77 C11.2 ; C11.2 73.56,16.94 ; C11.2 72.39,18.11 ; C11.2 71.22,16.94 ; 61.22,52.25 v1(61.63,51.84) ; v1(61.63,51.84) 62.04,51.43 ; v1(61.63,51.84) 61.22,51.43 ; v1(61.63,51.84) 62.04,52.25 ; 56.68,69.87 v1(57.09,70.28) ; v1(57.09,70.28) 57.5,69.87 ; v1(57.09,70.28) 57.5,70.69 ; v1(57.09,70.28) 56.68,70.69 ; U6.5 73.91,28.23 ; U6.5 75.04,27.1 ; U6.5 73.91,25.97 ; U6.5 72.78,27.1 ; 68.33,20.89 U5.1 ; U5.1 68.33,23.15 ; U5.1 67.2,22.02 ; U5.1 69.46,22.02 ; 21.59,15.77 C8.2 ; C8.2 20.42,16.94 ; C8.2 22.76,16.94 ; C8.2 21.59,18.11 ; v1(57.14,33.74) 57.55,33.33 ; v1(57.14,33.74) 56.73,33.33 ; v1(57.14,33.74) 57.55,34.15 ; v1(57.14,33.74) 56.73,34.15 ; U7.1 65.79,79.54 ; U7.1 66.92,78.41 ; U7.1 65.79,77.28 ; U7.1 64.66,78.41 ; J1.47 70.85,9.07 ; J1.47 69.85,10.07 ; J1.47 69.85,8.06 ; J1.47 68.85,9.07 ; 40.72,53.57 v1(41.14,53.16) ; v1(41.14,53.16) 40.72,52.75 ; v1(41.14,53.16) 41.55,52.75 ; v1(41.14,53.16) 41.55,53.57 ; v1(17.6,58.6) 18.01,59.01 ; v1(17.6,58.6) 17.19,59.01 ; v1(17.6,58.6) 17.19,58.19 ; v1(17.6,58.6) 18.01,58.19 ; 34.37,96.87 v1(34.79,96.46) ; v1(34.79,96.46) 35.2,96.87 ; v1(34.79,96.46) 34.37,96.05 ; v1(34.79,96.46) 35.2,96.05 ; v1(58.84,52.5) 59.25,52.09 ; v1(58.84,52.5) 59.25,52.91 ; v1(58.84,52.5) 58.43,52.09 ; v1(58.84,52.5) 58.43,52.91 ; v1(18.87,48.06) 19.28,48.47 ; v1(18.87,48.06) 18.46,48.47 ; v1(18.87,48.06) 18.46,47.65 ; v1(18.87,48.06) 19.28,47.65 ; 33.92,80.67 v1(34.33,81.08) ; v1(34.33,81.08) 34.74,81.49 ; v1(34.33,81.08) 34.74,80.67 ; v1(34.33,81.08) 33.92,81.49 ; 73.91,20.89 U6.1 ; U6.1 72.78,22.02 ; U6.1 73.91,23.15 ; U6.1 75.04,22.02 ; 70.24,78.41 U8.1 ; U8.1 71.37,77.28 ; U8.1 72.5,78.41 ; U8.1 71.37,79.54 ; v1(61.73,95.19) 62.15,94.78 ; v1(61.73,95.19) 61.32,94.78 ; v1(61.73,95.19) 62.15,95.6 ; v1(61.73,95.19) 61.32,95.6
  BOTTOM w0.254: v1(61.46,47.71) 61.89,47.28 61.89,47.12 60.79,46.02 C9.2 ; v1(25.54,86.08) 25.54,85.51 C12.2 ; v1(34.79,96.46) 35.45,97.12 35.45,97.15 34.51,98.09 C17.2 ; v1(49.03,83.12) 49.78,83.87 C2.2 ; C20.2 17.88,57.71 17.6,57.99 v1(17.6,58.6) ; v1(22.72,99.16) 22.72,98.59 C13.2 ; C6.2 46.6,102.3 v1(46.6,101.85) ; v1(14.74,94.74) 14.74,95.06 C14.2 ; C19.2 11.61,26.9 v1(11.61,27.53) ; C10.2 54.78,54.75 v1(54.91,54.75) ; v1(18.62,71.12) 18.62,71.98 18.82,72.19 C23.2 ; v1(72.78,98.46) 72.78,97.7 C24.2 ; C1.2 v1(53.21,34.35) ; C25.2 v1(45.72,64.26) ; C16.2 v1(42.67,54.43) ; C3.2 62.48,95.94 v1(61.73,95.19) ; v1(11.93,87.22) 11.93,86.91 C15.2 ; C21.2 v1(26.34,63.42) ; C7.2 61.73,84.14 v1(61.73,83.82) ; v1(11.61,42.77) 11.61,42.14 C22.2 ; v1(49.23,95.19) 50.04,96 C4.2 ; C18.2 v1(26.14,35.23) ; C26.2 v1(69.34,93.47)
VCC: length 253.2
  TOP w0.254: U16.32 v1(29.84,65.2) ; U11.42 52.43,33.62 52.3,33.74 v1(51.1,33.74) ; U11.21 v1(43.93,40.61) ; U3.16 v1(51.57,102.54) ; U1.16 v1(51.32,89.97) ; U12.14 v1(32.33,93.14) ; U17.20 v1(9.47,36.63) ; U14.20 v1(12.71,21.39) ; U20.14 v1(74.94,102.03) ; U13.32 v1(32.38,36.86) ; U22.16 v1(39.1,89.97) ; U4.16 v1(64.02,89.97) ; U11.48 56.39,30.81 56.53,30.67 v1(57.14,30.67) ; v1(47.49,30.67) 47.14,31.01 U11.34 ; U11.69 v1(58.53,46.56) ; U11.32 v1(45.82,30.62) ; U15.20 v1(21.18,62.66) ; U11.9 v1(44.21,48.54) ; U11.84 v1(55.73,54.75) ; U19.28 v1(44.18,70.28) ; U10.16 v1(9.64,81.08) ; U9.14 v1(17.03,100.76) ; U11.10 v1(41.14,47.88) ; U11.91 v1(51.1,54.75) ; U11.36 v1(48.46,31.23) ; U2.16 v1(64.02,102.03) ; U11.97 v1(47.14,54.75) ; U11.57 v1(58.94,38.63) ; U11.71 v1(58.84,47.88) ; U11.6 v1(43.93,50.52) ; U23.16 v1(27.67,89.97) ; U18.20 v1(21.09,77.27) ; U11.8 v1(41.41,49.2) ; U11.39 v1(50.44,31.23) ; U21.14 v1(20.59,93.14)
  VCC w0.254: 69.55,98.01 v1(69.96,98.42) ; v1(69.96,98.42) 69.55,98.84 ; v1(69.96,98.42) 70.37,98.84 ; v1(69.96,98.42) 70.37,98.01 ; v1(21.09,77.27) 21.51,76.86 ; v1(21.09,77.27) 20.68,77.68 ; v1(21.09,77.27) 20.68,76.86 ; v1(21.09,77.27) 21.51,77.68 ; v1(62.48,103.54) 62.89,103.13 ; v1(62.48,103.54) 62.07,103.95 ; v1(62.48,103.54) 62.89,103.95 ; v1(62.48,103.54) 62.07,103.13 ; 63.61,102.44 v1(64.02,102.03) ; v1(64.02,102.03) 64.43,101.62 ; v1(64.02,102.03) 64.43,102.44 ; v1(64.02,102.03) 63.61,101.62 ; v1(41.41,49.2) 41.83,48.79 ; v1(41.41,49.2) 41,48.79 ; v1(41.41,49.2) 41.83,49.61 ; v1(41.41,49.2) 41,49.61 ; 15.08,102.24 v1(15.49,101.83) ; v1(15.49,101.83) 15.08,101.42 ; v1(15.49,101.83) 15.9,101.42 ; v1(15.49,101.83) 15.9,102.24 ; 74.53,102.44 v1(74.94,102.03) ; v1(74.94,102.03) 74.53,101.62 ; v1(74.94,102.03) 75.35,101.62 ; v1(74.94,102.03) 75.35,102.44 ; v1(12.71,21.39) 13.12,20.98 ; v1(12.71,21.39) 13.12,21.8 ; v1(12.71,21.39) 12.3,21.8 ; v1(12.71,21.39) 12.3,20.98 ; v1(55.73,54.75) 56.14,54.34 ; v1(55.73,54.75) 55.32,55.16 ; v1(55.73,54.75) 55.32,54.34 ; v1(55.73,54.75) 56.14,55.16 ; v1(20.59,93.14) 21,93.55 ; v1(20.59,93.14) 20.18,93.55 ; v1(20.59,93.14) 21,92.73 ; v1(20.59,93.14) 20.18,92.73 ; 43.52,50.93 v1(43.93,50.52) ; v1(43.93,50.52) 44.34,50.11 ; v1(43.93,50.52) 43.52,50.11 ; v1(43.93,50.52) 44.34,50.93 ; v1(9.64,81.08) 10.05,81.49 ; v1(9.64,81.08) 9.23,81.49 ; v1(9.64,81.08) 10.05,80.67 ; v1(9.64,81.08) 9.23,80.67 ; 31.97,37.27 v1(32.38,36.86) ; v1(32.38,36.86) 31.97,36.45 ; v1(32.38,36.86) 32.8,36.45 ; v1(32.38,36.86) 32.8,37.27 ; 72.78,39.8 U6.15 ; U6.15 75.04,39.8 ; U6.15 73.91,40.93 ; U6.15 73.91,38.67 ; v1(21.18,62.66) 21.59,62.25 ; v1(21.18,62.66) 20.77,62.25 ; v1(21.18,62.66) 21.59,63.07 ; v1(21.18,62.66) 20.77,63.07 ; 43.77,70.69 v1(44.18,70.28) ; v1(44.18,70.28) 43.77,69.87 ; v1(44.18,70.28) 44.59,70.69 ; v1(44.18,70.28) 44.59,69.87 ; C11.1 63.4,16.94 ; C11.1 62.23,15.77 ; C11.1 61.06,16.94 ; C11.1 62.23,18.11 ; 10.43,9.07 J1.1 ; J1.1 11.43,8.06 ; J1.1 11.43,10.07 ; J1.1 12.43,9.07 ; 61.04,39.21 v1(61.46,38.8) ; v1(61.46,38.8) 61.04,38.39 ; v1(61.46,38.8) 61.87,39.21 ; v1(61.46,38.8) 61.87,38.39 ; 10.26,16.94 C8.1 ; C8.1 12.6,16.94 ; C8.1 11.43,15.77 ; C8.1 11.43,18.11 ; v1(39.1,89.97) 39.51,89.56 ; v1(39.1,89.97) 38.69,89.56 ; v1(39.1,89.97) 39.51,90.38 ; v1(39.1,89.97) 38.69,90.38 ; 33.12,58.22 Y1.14 ; Y1.14 34.29,57.05 ; Y1.14 35.46,58.22 ; Y1.14 34.29,59.39 ; 10.43,11.61 J1.2 ; J1.2 11.43,12.61 ; J1.2 12.43,11.61 ; J1.2 11.43,10.6 ; v1(32.33,93.14) 32.74,93.55 ; v1(32.33,93.14) 32.74,92.73 ; v1(32.33,93.14) 31.92,92.73 ; v1(32.33,93.14) 31.92,93.55 ; 50.91,89.56 v1(51.32,89.97) ; v1(51.32,89.97) 50.91,90.38 ; v1(51.32,89.97) 51.73,89.56 ; v1(51.32,89.97) 51.73,90.38 ; 47.07,31.08 v1(47.49,30.67) ; v1(47.49,30.67) 47.9,31.08 ; v1(47.49,30.67) 47.9,30.26 ; v1(47.49,30.67) 47.07,30.26 ; 58.12,46.97 v1(58.53,46.56) ; v1(58.53,46.56) 58.12,46.15 ; v1(58.53,46.56) 58.94,46.97 ; v1(58.53,46.56) 58.94,46.15 ; 44.03,97.49 v1(44.44,97.08) ; v1(44.44,97.08) 44.85,97.49 ; v1(44.44,97.08) 44.03,96.67 ; v1(44.44,97.08) 44.85,96.67 ; v1(41.14,47.88) 41.55,47.47 ; v1(41.14,47.88) 40.72,48.29 ; v1(41.14,47.88) 41.55,48.29 ; v1(41.14,47.88) 40.72,47.47 ; 43.8,48.95 v1(44.21,48.54) ; v1(44.21,48.54) 43.8,48.13 ; v1(44.21,48.54) 44.62,48.13 ; v1(44.21,48.54) 44.62,48.95 ; 19.15,78.93 v1(19.56,78.52) ; v1(19.56,78.52) 19.97,78.93 ; v1(19.56,78.52) 19.15,78.11 ; v1(19.56,78.52) 19.97,78.11 ; J1.3 13.97,10.07 ; J1.3 12.97,9.07 ; J1.3 14.97,9.07 ; J1.3 13.97,8.06 ; 50.69,33.33 v1(51.1,33.74) ; v1(51.1,33.74) 51.52,34.15 ; v1(51.1,33.74) 50.69,34.15 ; v1(51.1,33.74) 51.52,33.33 ; 10.77,79.73 v1(11.18,80.14) ; v1(11.18,80.14) 11.59,79.73 ; v1(11.18,80.14) 10.77,80.55 ; v1(11.18,80.14) 11.59,80.55 ; 10.77,19.77 v1(11.18,19.35) ; v1(11.18,19.35) 10.77,18.94 ; v1(11.18,19.35) 11.59,19.77 ; v1(11.18,19.35) 11.59,18.94 ; 70.24,60.63 U8.15 ; U8.15 71.37,59.5 ; U8.15 71.37,61.76 ; U8.15 72.5,60.63 ; 29.43,65.61 v1(29.84,65.2) ; v1(29.84,65.2) 30.26,64.79 ; v1(29.84,65.2) 29.43,64.79 ; v1(29.84,65.2) 30.26,65.61 ; v1(50.04,103.66) 50.45,103.25 ; v1(50.04,103.66) 50.45,104.07 ; v1(50.04,103.66) 49.63,104.07 ; v1(50.04,103.66) 49.63,103.25 ; v1(9.47,36.63) 9.88,36.22 ; v1(9.47,36.63) 9.06,37.04 ; v1(9.47,36.63) 9.06,36.22 ; v1(9.47,36.63) 9.88,37.04 ; 10.77,35.28 v1(11.18,35.69) ; v1(11.18,35.69) 11.59,35.28 ; v1(11.18,35.69) 10.77,36.1 ; v1(11.18,35.69) 11.59,36.1 ; 33.63,92.33 v1(34.04,91.92) ; v1(34.04,91.92) 33.63,91.51 ; v1(34.04,91.92) 34.45,92.33 ; v1(34.04,91.92) 34.45,91.51 ; 16.62,100.35 v1(17.03,100.76) ; v1(17.03,100.76) 17.44,100.35 ; v1(17.03,100.76) 16.62,101.17 ; v1(17.03,100.76) 17.44,101.17 ; 62.07,90.5 v1(62.48,90.91) ; v1(62.48,90.91) 62.89,91.32 ; v1(62.48,90.91) 62.07,91.32 ; v1(62.48,90.91) 62.89,90.5 ; v1(41.41,50.36) 41.83,50.77 ; v1(41.41,50.36) 41,50.77 ; v1(41.41,50.36) 41,49.95 ; v1(41.41,50.36) 41.83,49.95 ; v1(44.52,69.22) 44.93,69.63 ; v1(44.52,69.22) 44.11,69.63 ; v1(44.52,69.22) 44.11,68.8 ; v1(44.52,69.22) 44.93,68.8 ; v1(31.19,36.37) 31.6,35.96 ; v1(31.19,36.37) 30.78,35.96 ; v1(31.19,36.37) 30.78,36.78 ; v1(31.19,36.37) 31.6,36.78 ; 43.52,41.03 v1(43.93,40.61) ; v1(43.93,40.61) 44.34,40.2 ; v1(43.93,40.61) 44.34,41.03 ; v1(43.93,40.61) 43.52,40.2 ; 21.81,92.49 v1(22.23,92.08) ; v1(22.23,92.08) 22.64,92.49 ; v1(22.23,92.08) 22.64,91.66 ; v1(22.23,92.08) 21.81,91.66 ; C5.1 62.23,79.71 ; C5.1 63.4,78.54 ; C5.1 61.06,78.54 ; C5.1 62.23,77.37 ; 27.26,90.38 v1(27.67,89.97) ; v1(27.67,89.97) 27.26,89.56 ; v1(27.67,89.97) 28.08,90.38 ; v1(27.67,89.97) 28.08,89.56 ; 25.62,90.62 v1(26.04,91.03) ; v1(26.04,91.03) 26.45,91.44 ; v1(26.04,91.03) 25.62,91.44 ; v1(26.04,91.03) 26.45,90.62 ; 58.43,47.47 v1(58.84,47.88) ; v1(58.84,47.88) 58.43,48.29 ; v1(58.84,47.88) 59.25,48.29 ; v1(58.84,47.88) 59.25,47.47 ; 58.53,39.04 v1(58.94,38.63) ; v1(58.94,38.63) 59.35,39.04 ; v1(58.94,38.63) 58.53,38.22 ; v1(58.94,38.63) 59.35,38.22 ; U7.15 65.79,61.76 ; U7.15 64.66,60.63 ; U7.15 65.79,59.5 ; U7.15 66.92,60.63 ; v1(64.02,89.97) 64.43,90.38 ; v1(64.02,89.97) 63.61,89.56 ; v1(64.02,89.97) 63.61,90.38 ; v1(64.02,89.97) 64.43,89.56 ; U5.15 69.46,39.8 ; U5.15 68.33,38.67 ; U5.15 68.33,40.93 ; U5.15 67.2,39.8 ; v1(19.61,63.73) 20.02,63.32 ; v1(19.61,63.73) 19.2,64.14 ; v1(19.61,63.73) 19.2,63.32 ; v1(19.61,63.73) 20.02,64.14 ; J1.4 13.97,12.61 ; J1.4 12.97,11.61 ; J1.4 13.97,10.6 ; J1.4 14.97,11.61 ; 50.69,54.34 v1(51.1,54.75) ; v1(51.1,54.75) 51.52,55.16 ; v1(51.1,54.75) 50.69,55.16 ; v1(51.1,54.75) 51.52,54.34 ; v1(49.78,90.91) 50.19,90.5 ; v1(49.78,90.91) 50.19,91.32 ; v1(49.78,90.91) 49.37,90.5 ; v1(49.78,90.91) 49.37,91.32 ; v1(73.41,103.1) 73.82,103.51 ; v1(73.41,103.1) 73.82,102.69 ; v1(73.41,103.1) 73,103.51 ; v1(73.41,103.1) 73,102.69 ; v1(51.57,102.54) 51.99,102.95 ; v1(51.57,102.54) 51.16,102.95 ; v1(51.57,102.54) 51.99,102.13 ; v1(51.57,102.54) 51.16,102.13
  BOTTOM w0.254: C17.1 v1(34.04,91.92) ; C1.1 48.54,33.1 v1(48.54,34.35) ; C24.1 v1(73.41,103.1) ; C4.1 v1(50.04,103.66) ; C21.1 30.3,63.42 v1(31.29,64.41) ; C7.1 v1(62.48,90.91) ; v1(41.41,50.36) 42.67,49.1 C16.1 ; v1(31.19,36.37) 31.6,36.37 32.26,35.71 C18.1 ; C19.1 v1(11.18,19.35) ; v1(61.46,38.8) 60.33,39.93 C9.1 ; C14.1 v1(15.49,101.83) ; C26.1 69.96,98.87 v1(69.96,98.42) ; v1(19.61,63.73) 19.61,62.71 C20.1 ; C2.1 v1(49.78,90.91) ; C15.1 v1(11.18,80.14) ; v1(44.44,97.08) 44.44,97.84 44.56,97.97 C6.1 ; C10.1 v1(48.9,57.26) ; C13.1 v1(22.23,92.08) ; C23.1 v1(19.56,78.52) ; C3.1 v1(62.48,103.54) ; C22.1 v1(11.18,35.69) ; C12.1 v1(26.04,91.03) ; C25.1 44.65,69.22 v1(44.52,69.22)
A1: length 161.8
  TOP w0.127: 23.15,25.59 23.43,25.59 23.67,25.83 U13.11 ; 23.15,25.59 22.54,26.2 22.54,38.37 23.81,39.64 v1(25.72,39.64) 39.05,39.64 42.01,42.6 U11.18 ; 23.15,25.59 v1(23.15,25.59) ; U2.13 60.96,98.22 60.45,98.73 v1(52.07,98.73) ; v1(25.96,56.46) 25.96,57.07 25.72,57.32 25.72,63.61 28.07,65.96 37.6,65.96 39.38,67.74 39.38,70.54 41.92,73.08 44.3,73.08 44.55,73.33 44.55,73.81 44.3,74.07 v1(40.23,74.07) 38.34,74.07 37.1,72.82 U16.11
  BOTTOM w0.127: v1(25.96,56.46) 25.96,55.85 25.72,55.61 v1(25.72,39.64) ; v1(23.15,25.59) 23.15,10.05 J1.11 ; v1(52.07,98.73) 50.06,100.74 40.74,100.74 40.23,100.23 v1(40.23,74.07)
A2: length 155.5
  TOP w0.127: U4.3 v1(58.92,87.43) ; 61.28,74.92 61.77,74.92 62.03,75.17 62.03,75.68 61.8,75.91 46.1,75.91 44.79,74.6 36.02,74.6 35.76,74.35 35.76,72.21 36.42,71.55 U16.10 ; 61.28,74.92 61.28,66.45 62.94,64.78 62.94,37.63 62.46,37.15 ; 61.28,74.92 v1(57.92,74.92) ; U11.51 v1(61.46,34.67) ; 62.46,37.15 62.46,31.98 60.64,30.16 60.64,27.42 59.69,26.47 33.48,26.47 32.84,27.1 U13.10 v1(24.37,27.1) ; 62.46,37.15 v1(61.46,37.15)
  BOTTOM w0.127: v1(57.92,74.92) 57.92,86.44 v1(58.92,87.43) ; v1(61.46,34.67) v1(61.46,37.15) ; v1(24.37,27.1) 24.37,11.85 J1.12
A3: length 154.7
  TOP w0.127: 35.36,70.92 24.5,70.92 23.61,70.03 v1(23.61,50.08) ; 35.36,70.92 35.36,74.51 35.7,74.85 43.7,74.85 43.94,75.1 v1(44.55,75.1) ; 35.36,70.92 35.45,70.83 35.45,70.6 35.76,70.28 U16.9 ; 24.63,31.43 24.63,30.43 24.78,30.28 26.21,30.28 26.39,30.1 26.39,28.99 25.77,28.37 U13.9 ; 24.63,31.43 24.63,34.39 v1(24.69,34.46) ; 24.63,31.43 24.74,31.55 25.91,31.55 26.03,31.43 29.84,31.43 30.05,31.64 32.07,31.64 32.55,31.15 34.02,31.15 36.04,29.13 57.51,29.13 58.97,30.59 58.97,35.23 59.07,35.33 U11.52 ; U1.13 v1(46.98,86.16)
  BOTTOM w0.127: J1.13 25.34,10.4 25.34,27.97 24.69,28.61 v1(24.69,34.46) 24.69,49 v1(23.61,50.08) ; v1(44.55,75.1) 44.55,83.73 v1(46.98,86.16)
A4: length 171.2
  TOP w0.127: v1(30.32,53.09) 26.09,53.09 24.37,54.8 24.37,68 24.75,68.38 35.08,68.38 v1(35.71,69.01) U16.8 ; v1(41.45,29.63) 57.34,29.63 58.71,31 58.71,35.64 59.07,35.99 U11.53 ; U13.8 25.13,29.64 23.87,28.38 23.87,26.85 24.26,26.47 25.9,26.47 26.02,26.59 v1(26.77,26.59) v1(30.32,26.59) 31.71,25.2 37.22,25.2 37.35,25.32 v1(41.45,25.32) ; U3.13 v1(48.12,98.73)
  BOTTOM w0.127: v1(30.32,53.09) v1(30.32,26.59) ; J1.14 26.77,11.71 v1(26.77,26.59) ; v1(48.12,98.73) 48.12,100.23 47.87,100.48 43.76,100.48 41.73,98.45 41.73,69.27 41.48,69.01 v1(35.71,69.01) ; v1(41.45,29.63) v1(41.45,25.32)
A5: length 161.1
  TOP w0.127: 37.67,69.65 24.75,69.65 24.12,69.01 24.12,54.22 26,52.34 v1(31.05,52.34) ; 37.67,69.65 37.67,68.63 U16.7 ; 37.67,69.65 37.67,71.86 39.38,73.57 v1(44.06,73.57) ; v1(30.81,31.14) 30.32,30.64 27.76,30.64 ; 27.76,30.64 27.5,30.91 U13.7 ; 27.76,30.64 27.76,28.63 28.78,27.61 59.13,27.61 59.79,28.27 59.79,32.08 60.53,32.82 61.52,32.82 61.95,33.25 61.95,36.03 61.33,36.65 U11.54 ; U1.3 v1(44.06,87.43)
  BOTTOM w0.127: v1(31.05,52.34) 31.05,51.73 30.7,51.37 30.7,31.25 v1(30.81,31.14) 32.7,29.25 32.7,11.04 31.94,10.27 30.42,10.27 J1.15 ; v1(44.06,87.43) v1(44.06,73.57)
A6: length 159.5
  TOP w0.127: v1(29.1,31.93) 28.84,32.18 U13.6 ; U11.55 v1(58.85,37.31) ; U16.6 33.67,66.47 v1(33.16,66.98) 26.02,66.98 25.9,67.11 24.78,67.11 24.63,66.95 24.63,55.36 26.15,53.84 v1(29.1,53.84) ; U3.3 v1(40.73,100) ; v1(29.1,28.11) 29.71,28.11 29.95,27.86 58,27.86 58.24,28.11 v1(58.85,28.11)
  BOTTOM w0.127: v1(58.85,37.31) v1(58.85,28.11) ; J1.16 29.1,11.72 v1(29.1,28.11) v1(29.1,31.93) v1(29.1,53.84) ; v1(40.73,100) 40.73,73.83 39.97,73.06 35.19,73.06 33.16,71.03 v1(33.16,66.98)
A7: length 166.9
  TOP w0.127: U16.5 35.84,65.2 35.69,65.05 35.69,64.95 ; 35.69,64.95 35.69,58.24 33.91,56.46 v1(32.31,56.46) ; 35.69,64.95 v1(32.03,64.95) ; v1(39.74,100.51) 48.63,100.51 49.64,99.49 U2.3 ; U13.5 27.29,33.45 28.3,32.45 v1(33.08,32.45) 33.99,31.55 43.6,31.55 45.15,30 57.19,30 58.2,31.01 58.2,37.5 58.67,37.97 U11.56
  BOTTOM w0.127: v1(32.03,64.95) 32.03,72.3 34.06,74.33 37.96,74.33 39.74,76.11 v1(39.74,100.51) ; v1(32.31,56.46) 32.31,39.14 33.08,38.37 v1(33.08,32.45) 33.08,10.45 31.75,9.12 J1.17
A8: length 218.7
  TOP w0.127: U13.4 27.3,36.25 27.69,36.63 v1(29.82,36.63) ; v1(29.82,56.46) 34.92,61.57 U16.4 ; U4.13 61.47,86.16 59.44,84.12 57.12,84.12 56.52,83.52 56.52,82.37 57.18,81.71 75.13,81.71 75.77,81.08 75.77,20.73 73.09,18.05 v1(61.39,18.05) 59.05,15.71 54.94,15.71 54.9,15.67 53.98,15.67 51.23,12.93 33.07,12.93 J1.18 ; U11.58 v1(62.45,39.29)
  BOTTOM w0.127: J1.18 31.75,24.45 29.82,26.38 v1(29.82,36.63) v1(29.82,56.46) ; v1(62.45,39.29) 62.45,19.11 v1(61.39,18.05)
A9: length 158
  TOP w0.127: v1(35.24,33.45) U13.29 44.25,33.45 44.5,33.71 45.41,33.71 48.97,37.26 54.32,37.26 57.01,39.95 U11.59 61.47,39.95 62.62,41.11 62.62,64.67 60.9,66.4 60.9,72.49 60.02,73.37 v1(59.41,73.37) ; v1(35.24,55.07) 25.46,55.07 25.21,55.32 25.21,64.96 U16.29 ; U2.12 v1(59.41,96.95)
  BOTTOM w0.127: J1.19 35.24,10.02 v1(35.24,33.45) v1(35.24,55.07) ; v1(59.41,96.95) v1(59.41,73.37)
A10: length 157.1
  TOP w0.127: U11.60 v1(56.64,40.61) ; U4.4 v1(52.84,86.16) ; v1(33.57,55.56) 33.45,55.45 26.23,55.45 25.46,56.21 25.46,63.89 26.39,64.82 26.39,65.85 25.77,66.47 U16.28 ; v1(34.29,28.88) 56.4,28.88 v1(56.64,28.64) ; v1(34.29,32.44) 34.54,32.18 U13.28
  BOTTOM w0.127: v1(52.84,86.16) 52.84,71.75 53.35,71.25 53.35,59.28 54.88,57.76 55.38,57.76 56.64,56.5 v1(56.64,40.61) v1(56.64,28.64) ; v1(33.57,55.56) 33.57,54.95 33.34,54.72 33.34,41.86 34.29,40.91 v1(34.29,32.44) v1(34.29,28.88) J1.20
A11: length 153.2
  TOP w0.127: U16.24 v1(34.42,71.55) ; v1(60.33,31.55) 60.33,27.74 59.69,27.1 v1(37.85,27.1) U13.24 ; U11.61 v1(61.95,41.27) ; v1(42.98,83.35) 43.59,83.35 43.83,83.11 45.95,83.11 47.73,84.89 U1.12 v1(55.11,84.89)
  BOTTOM w0.127: v1(34.42,71.55) 34.42,69.53 35.43,68.52 41.48,68.52 42.24,69.28 42.24,81.27 42.98,82 v1(42.98,83.35) ; v1(60.33,31.55) 61.32,31.55 61.95,32.18 v1(61.95,41.27) 61.95,42.84 60.93,43.85 59.05,43.85 58.04,44.87 58.04,57.87 55.11,60.81 v1(55.11,84.89) ; v1(37.85,27.1) 37.85,10.08 J1.21
A12: length 139.3
  TOP w0.127: U11.62 v1(52.35,41.94) ; v1(52.35,28.38) v1(37.85,28.38) ; U3.12 v1(48.49,97.46) ; U16.27 v1(34.91,67.74) ; U13.27 v1(37.85,30.91)
  BOTTOM w0.127: 48.49,66.73 52.35,62.87 v1(52.35,41.94) v1(52.35,28.38) ; 48.49,66.73 v1(48.49,97.46) ; 48.49,66.73 35.92,66.73 v1(34.91,67.74) ; v1(37.85,30.91) v1(37.85,28.38) 37.34,27.88 37.34,13.18 36.83,12.67 J1.22
A13: length 137.2
  TOP w0.127: 38.63,34.06 34.4,34.06 33.91,33.57 29.25,33.57 v1(28.57,34.24) U13.3 ; 38.63,34.06 v1(38.63,35.05) ; 38.63,34.06 43.99,34.06 50.27,40.34 50.27,40.94 52.58,43.26 U11.64 ; v1(28.14,55.94) 28.14,59.68 27.94,59.88 27.94,64.02 28.09,64.17 29.08,64.17 29.21,64.05 29.21,62.67 29.48,62.41 33.03,62.41 33.66,63.03 U16.3 v1(33.66,64.41) ; U1.4 v1(43.47,86.16)
  BOTTOM w0.127: v1(28.14,55.94) 28.57,55.51 28.57,42.81 28.64,42.75 28.64,42.34 28.57,42.28 28.57,41.54 28.64,41.48 28.64,41.07 28.57,41.01 v1(28.57,34.24) ; J1.23 40.32,10.02 40.32,34.38 39.65,35.05 v1(38.63,35.05) ; v1(43.47,86.16) 43.47,81.97 42.49,80.99 42.49,68.26 42.47,68.24 34.67,68.24 33.66,67.22 v1(33.66,64.41)
A14: length 141.3
  TOP w0.127: U3.4 v1(41.24,98.73) ; v1(41.24,69.51) 41.24,67.23 39.71,65.71 28.91,65.71 27.3,64.11 U16.30 27.3,59.42 27.62,59.11 v1(27.62,56.46) ; v1(27.62,37.35) 34.4,37.35 34.92,36.83 U13.30 34.98,35.36 37.03,35.36 37.24,35.56 39.17,35.56 39.37,35.36 v1(39.37,34.56) 39.98,34.56 40.22,34.32 43.69,34.32 43.69,34.37 44.65,35.33 44.65,37.03 51.54,43.92 U11.65
  BOTTOM w0.127: v1(41.24,69.51) v1(41.24,98.73) ; J1.24 v1(39.37,34.56) ; v1(27.62,56.46) v1(27.62,37.35)
A15: length 177.7
  TOP w0.127: v1(32.83,55.94) 29.59,55.94 28.57,56.96 U16.31 ; v1(33.66,16.8) v1(42.13,16.8) v1(59.44,16.8) ; U11.66 v1(57.54,44.58) ; U13.31 v1(33.66,34.06) ; U2.4 v1(53.84,98.22)
  BOTTOM w0.127: v1(53.84,98.22) 53.84,59.28 54.6,58.52 56.78,58.52 57.54,57.76 v1(57.54,44.58) 57.54,43.95 58.86,42.63 58.86,40.21 59.44,39.64 v1(59.44,16.8) ; v1(33.66,16.8) v1(33.66,34.06) 33.66,39.64 32.83,40.46 v1(32.83,55.94) ; J1.25 42.86,10.02 42.86,16.07 v1(42.13,16.8)
A16: length 44.9
  TOP w0.127: U4.12 61.86,84.89 61.21,84.24 61.21,83.81 60.53,83.12 v1(58.92,83.12) ; U11.70 61.72,47.22 62.13,47.63 v1(62.13,63.92)
  BOTTOM w0.127: v1(62.13,63.92) 60.96,63.92 58.42,66.46 58.42,82.63 v1(58.92,83.12)
ADDR0: length 78.8
  TOP w0.127: U2.9 v1(66.55,93.14) ; U7.11 U8.11 ; U5.11 U6.11
  BOTTOM w0.127: U6.11 74.87,35.67 74.87,64.95 74.1,65.71 U8.11 70.4,66.69 70.4,89.29 v1(66.55,93.14)
ADDR1: length 67.7
  TOP w0.127: U4.7 v1(61.73,82.35) ; U8.12 v1(69.65,64.44) U7.12
  BOTTOM w0.127: v1(61.73,82.35) 66.81,82.35 69.65,79.51 v1(69.65,64.44) 69.65,35.99 ; U6.12 69.65,35.99 ; 69.65,35.99 U5.12
ADDR2: length 73.8
  TOP w0.127: U6.13 U5.13 65.6,37.26 64.33,38.53 64.33,58.03 65.6,59.3 65.85,59.3 66.74,60.19 66.74,63.17 ; 66.74,63.17 U8.13 ; 66.74,63.17 U7.13 ; U1.9 v1(56.35,81.08)
  BOTTOM w0.127: U7.13 58.64,63.17 56.35,65.46 56.35,66.57 56.22,66.7 56.22,67.11 56.35,67.24 v1(56.35,81.08)
ADDR3: length 83.5
  TOP w0.127: U6.14 U5.14 ; U8.14 U7.14 ; U3.9 v1(55.33,93.65)
  BOTTOM w0.127: 64.83,61.9 57.12,61.9 55.6,63.42 55.6,92.77 55.33,93.04 v1(55.33,93.65) ; 64.83,61.9 U7.14 ; 64.83,61.9 64.83,39.48 U5.14
ADDR4: length 82.2
  TOP w0.127: U6.16 U5.16 ; U1.7 46.9,82.35 48.76,80.49 74.02,80.49 75.12,79.39 75.12,60.57 U8.16 U7.16
  BOTTOM w0.127: U7.16 67.25,58.28 67.25,42.53 U5.16
ADDR5: length 87.2
  TOP w0.127: U3.7 45.85,94.92 49.11,91.66 v1(59.91,91.66) ; U5.17 U6.17 ; U8.17 U7.17
  BOTTOM w0.127: v1(59.91,91.66) 59.91,71.42 58.81,70.33 58.81,66.95 61.1,64.67 65.68,64.67 67.25,63.11 68.52,63.11 69.28,62.34 69.28,61.33 68.52,60.57 68.01,60.57 65.79,58.34 U7.17 ; U8.17 72.58,56.88 72.58,43.68 U6.17
ADDR6: length 78.8
  TOP w0.127: U6.18 U5.18 64.83,44.56 64.83,56.06 65.6,56.82 U7.18 U8.18 ; U2.7 v1(60.9,94.41)
  BOTTOM w0.127: v1(60.9,94.41) 60.9,83.86 61.66,83.1 69.38,83.1 70.14,82.33 70.14,60.31 71.16,59.3 71.92,59.3 73.91,57.3 U8.18
ADDR7: length 63.3
  TOP w0.127: U7.19 U8.19 72.33,55.55 ; U4.9 74.5,81.08 75.37,80.2 75.37,56.82 74.1,55.55 72.33,55.55 ; 72.33,55.55 72.33,49.39 73.86,47.85 73.86,44.93 U6.19 U5.19
ADSL: length 92.6
  TOP w0.127: U19.17 57.59,71.55 60.13,69.01 v1(60.13,56.65) 59.05,55.57 59.05,54.84 57.4,53.19 57.4,46.6 56.13,45.33 45.69,45.33 44.28,43.92 U11.16
  BOTTOM w0.127: v1(60.13,56.65) 63.69,53.1 63.69,15.23 J1.46
BHEL: length 87.5
  TOP w0.127: U19.10 53.34,62.85 51.28,60.79 45.72,60.79 43.18,58.25 v1(43.18,55.16) ; U11.19 v1(44.42,41.94)
  BOTTOM w0.127: J1.42 60.9,10.27 60.9,8.88 59.88,7.86 43.75,7.86 43.24,8.37 43.24,40.75 v1(44.42,41.94) 44.42,42.55 44.7,42.82 44.7,53.63 v1(43.18,55.16)
BLEL: length 99
  TOP w0.127: v1(61.61,57.64) 61.61,55.59 60.45,54.43 59.44,54.43 57.91,52.91 57.91,46.28 56.71,45.07 46.71,45.07 44.89,43.26 U11.17 ; U19.9 52.07,64.11 52.71,64.75 53.89,64.75 53.98,64.66 53.98,63 55.94,61.04 v1(57.57,61.04)
  BOTTOM w0.127: J1.43 65.98,10.27 67.5,10.27 68.26,11.04 68.26,17.64 66.99,18.91 66.99,33.64 65.98,34.66 65.72,34.66 64.45,35.93 64.45,56.88 63.69,57.64 v1(61.61,57.64) 58.22,61.04 v1(57.57,61.04)
CAS0L: length 74
  TOP w0.127: v1(59.4,57.15) 59.4,57.76 59.8,58.17 59.8,68.31 57.26,70.85 51.3,70.85 48.26,73.89 U19.24 ; U6.2 U5.2
  BOTTOM w0.127: U5.2 65.79,22.23 65.07,21.51 64.52,21.51 63.94,22.09 63.94,56.9 63.69,57.15 v1(59.4,57.15)
CAS1L: length 26.2
  TOP w0.127: v1(61.53,75.41) 49.77,75.41 49.53,75.17 U19.23 ; U8.2 U7.2
  BOTTOM w0.127: U7.2 63.26,77.14 v1(61.53,75.41)
CLEAR: length 69.6
  TOP w0.127: v1(54.61,79.64) 54.61,79.6 v1(19.48,79.6) ; U19.19 v1(54.61,73.04) ; 19.25,85.52 v1(19.25,82.35) ; 19.25,85.52 15.04,85.52 14.4,84.89 14.4,82.78 14.83,82.35 U10.2 U10.1 ; 19.25,85.52 19.25,93.28 20.38,94.41 U21.13
  BOTTOM w0.127: v1(54.61,73.04) v1(54.61,79.64) ; v1(19.48,79.6) 19.48,82.12 v1(19.25,82.35)
CLK1+: length 14.6
  TOP w0.127: U23.1 24.55,89.97 25.18,89.33 27.17,89.33 27.22,89.38 v1(31.57,89.38) 31.57,88.77 31.65,88.7 U22.2
  BOTTOM w0.127: v1(31.57,89.38) 31.57,90 31.92,90.35 R2.1
CLK1-: length 24.3
  TOP w0.127: U23.2 20.71,88.7 20.02,89.4 20.02,90.42 20.62,91.03 23.7,91.03 24.33,91.67 32.82,91.67 34.37,90.12 v1(34.37,88.01) 33.78,87.43 U22.3
  BOTTOM w0.127: R2.2 34.12,87.05 34.37,87.29 v1(34.37,88.01)
CLK2: length 136.6
  TOP w0.305: U10.4 17.14,84.89 17.98,84.05 17.98,82.14 19.48,80.64 19.91,80.64 20.32,80.24 v1(43.38,80.24) ; v1(40.18,55.91) 40.18,62.41 42.98,65.2 42.98,66.95 43.76,67.74 U19.2 v1(46.99,67.74) ; J1.5 16.51,9.12 17.78,10.39 17.78,13.56 19.48,15.27 v1(36.36,15.27) ; v1(40.18,44.58) U11.15 v1(44.06,44.58)
  BOTTOM w0.305: v1(46.99,67.74) 44.96,67.74 43.38,69.32 43.38,73.24 43.35,73.28 43.35,73.87 43.38,73.9 v1(43.38,80.24) ; v1(44.06,44.58) 40.75,41.27 39.46,41.27 39.41,41.33 38.33,41.33 38.1,41.1 R1.2 36.88,39.42 36.36,38.9 v1(36.36,15.27) ; v1(40.18,55.91) v1(40.18,44.58)
CLK2+: length 23.2
  TOP w0.127: v1(25.46,81.78) 24.56,82.68 24.56,86.36 25.63,87.43 U23.14 27.55,87.43 29.41,85.56 29.41,85.55 31.34,83.62 U22.6
  BOTTOM w0.127: R3.1 25.91,81.33 v1(25.46,81.78)
CLK2-: length 11.6
  TOP w0.127: U22.5 v1(31.71,84.89) ; U23.15 v1(31,88.7)
  BOTTOM w0.127: R3.2 32.12,85.53 31.71,85.53 ; 31.71,85.53 31.71,87.98 v1(31,88.7) ; 31.71,85.53 v1(31.71,84.89)
CLK3+: length 27.9
  TOP w0.127: U22.10 38.29,82.35 38.94,82.99 38.94,86.72 38.86,86.79 30.61,86.79 29.34,88.06 25.49,88.06 22.9,85.47 v1(22.9,83.62) U23.6
  BOTTOM w0.127: v1(22.9,83.62) 22.9,84.43 22.69,84.63 R4.1
CLK3-: length 19.1
  TOP w0.127: U23.7 v1(22.9,82.35) ; U22.11 37.1,83.62 36.54,83.06 v1(36.54,82.35)
  BOTTOM w0.127: R4.2 22.61,82.35 v1(22.9,82.35) v1(36.54,82.35)
CLK4+: length 18.3
  TOP w0.127: U22.14 v1(35.97,87.43) ; v1(35.15,83.03) 35.1,82.98 31.75,82.98 31.12,82.35 U23.10
  BOTTOM w0.127: 35.97,83.36 35.97,83.24 35.76,83.03 v1(35.15,83.03) ; 35.97,83.36 v1(35.97,87.43) ; 35.97,83.36 36.66,83.36 37.68,82.35 R5.1
CLK4-: length 16.9
  TOP w0.127: U23.9 31.75,81.08 32.39,81.71 34.77,81.71 35.73,82.66 35.73,83.93 v1(36.54,84.75) 36.54,85.6 37.1,86.16 U22.13
  BOTTOM w0.127: v1(36.54,84.75) 36.54,85.45 36.74,85.65 R5.2
CLRCNT: length 69.5
  TOP w0.127: 31.55,97.59 25.43,97.59 24.79,96.95 U21.11 ; 31.55,97.59 31.55,96.91 32.78,95.68 U12.12 36.46,95.68 37.73,94.41 U12.2 ; 31.55,97.59 31.55,102.03 32.56,103.05 69.22,103.05 69.72,102.54 69.72,100.76 ; 69.72,100.76 70.99,99.49 U20.12 ; 69.72,100.76 U20.2
D0: length 109
  TOP w0.127: U18.2 10.16,76 9.46,75.3 9.46,68.12 9.84,67.74 11.37,67.74 11.86,67.25 11.86,61.77 11.48,61.39 U15.2 9.6,61.39 9.21,61 9.21,53.26 9.46,53.01 16.14,53.01 19.57,49.58 31.5,49.58 v1(35.74,53.82) ; U11.1 v1(38.61,53.82) ; v1(39.12,40.61) v1(39.12,44.28)
  BOTTOM w0.127: J1.26 41.91,12.67 41.63,12.95 41.63,20.54 42.2,21.11 42.2,37.53 v1(39.12,40.61) ; v1(35.74,53.82) v1(38.61,53.82) 39.62,52.81 39.62,48.55 38.72,47.65 38.72,44.68 v1(39.12,44.28)
